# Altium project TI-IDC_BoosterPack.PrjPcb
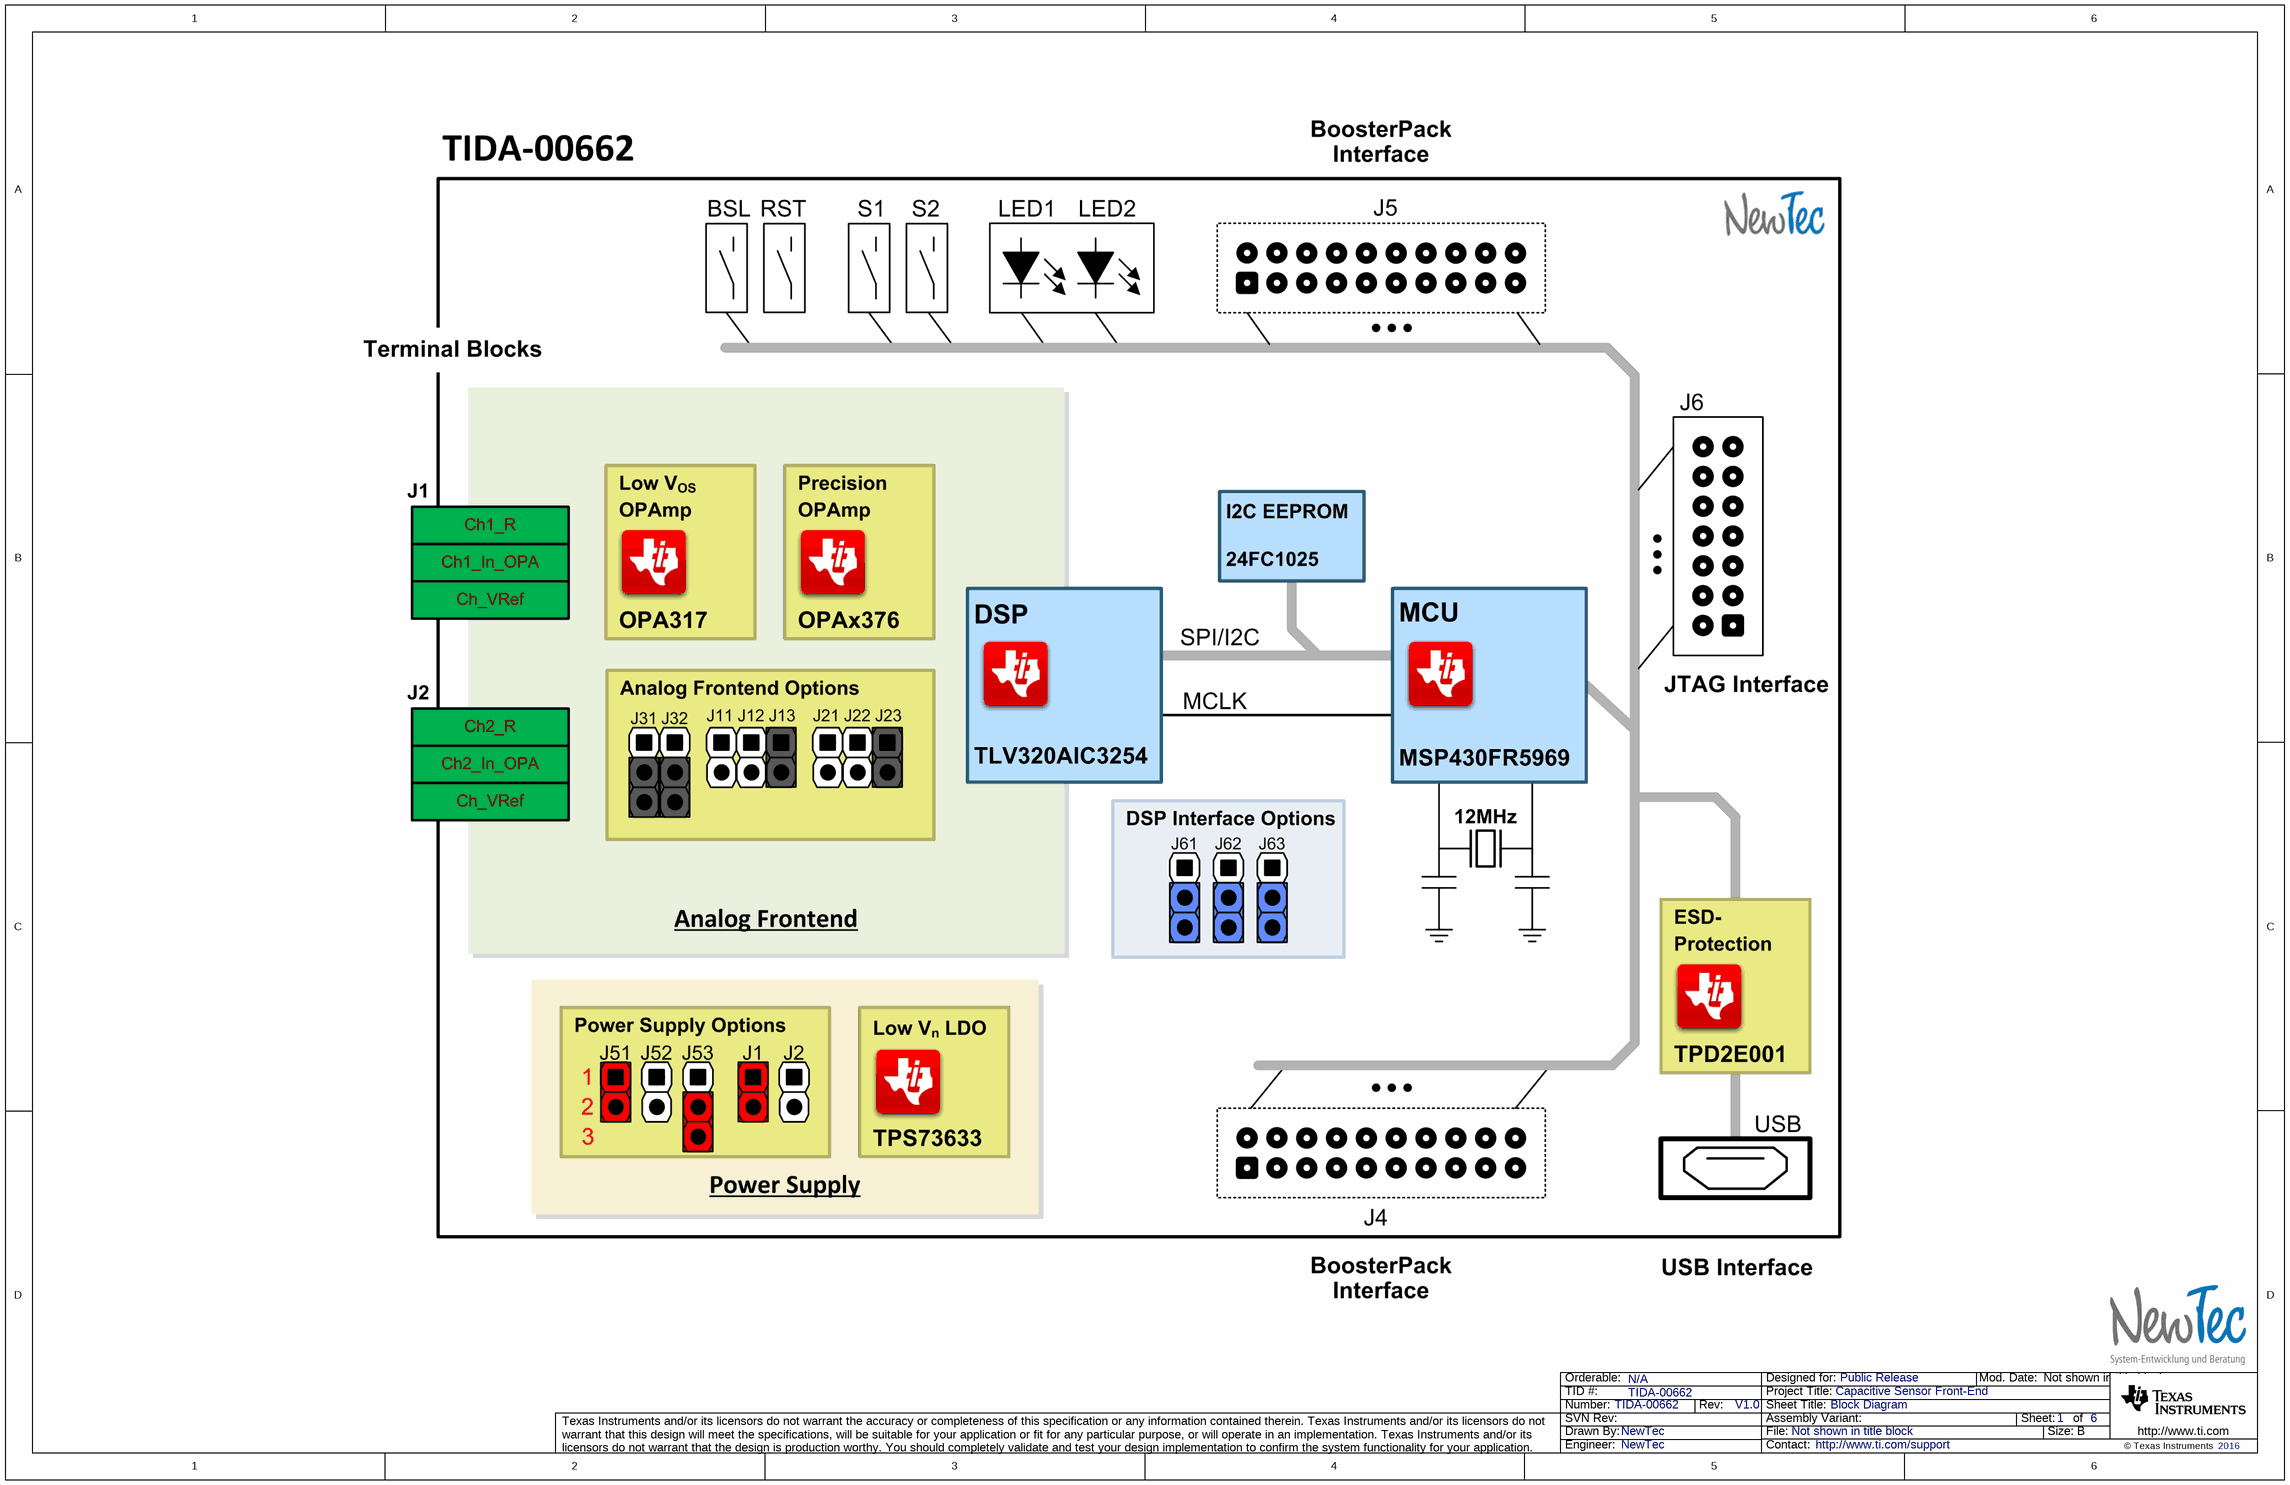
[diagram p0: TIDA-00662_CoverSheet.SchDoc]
CopyrightYear: 2016; EVM_Orderable: N/A; PCB_Layout: NewTec; PCB_Rev: V1.0; PRJ_Customer: Public Release; PRJ_Engineer: NewTec; PRJ_Number: TIDA-00662; PRJ_Title: Capacitive Sensor Front-End; SCH_Rev: V1.0; TechSupport: http://www.ti.com/support; TID: TIDA-00662
6 sheets, 125 parts. Net scope: flat (ports and power ports of the same name join across sheets).
Board file: TIDA-00662_IDC-BosterPack.PcbDoc
Sheets:
  TIDA-00662_CoverSheet.SchDoc
  TIDA-00662_AIC3254.SchDoc
  TIDA-00662_MCU.SchDoc
  TIDA-00662_ExternalInterfaces.SchDoc
  TIDA-00662_PowerSupply.SchDoc
  TIDA-00662_TID_Hardware.SchDoc

## Sheet TIDA-00662_CoverSheet.SchDoc: Block Diagram
size 431 x 279 mm; Date: Not shown in title block; ApprovedBy: Not shown in title block; CheckedBy: Not shown in title block; Author: Not shown in title block; CompanyName: Not shown in title block; DrawnBy: NewTec; Engineer: Not shown in title block; Organization: Not shown in title block; Address1: Not shown in title block; Address2: Not shown in title block; Address3: Not shown in title block; Address4: Not shown in title block; DocumentNumber: 1; Revision: Use project parameter SCH_Rev; SheetNumber: 1; SheetTotal: 6; PageSetup: Record=PageOptions¦CenterHorizontal=True¦CenterVertical=True¦PrintScale=1.00¦XCorrection=1.00¦YCorrection=1.00¦PrintKind=0¦BorderSize=5000000¦LeftOffset=0¦BottomOffset=0¦Orientation=2¦PaperLength=1000¦PaperWidth=1000¦Scale=100¦PaperSource=15¦PrintQuality=600¦MediaType=1¦DitherType=10¦PaperKind=Letter¦PrintScaleMode=1

## Sheet TIDA-00662_AIC3254.SchDoc: Sensor Front-End
size 431 x 279 mm; Date: Not shown in title block; ApprovedBy: Not shown in title block; CheckedBy: Not shown in title block; Author: Not shown in title block; CompanyName: Not shown in title block; DrawnBy: NewTec; Engineer: Not shown in title block; Organization: Not shown in title block; Address1: Not shown in title block; Address2: Not shown in title block; Address3: Not shown in title block; Address4: Not shown in title block; DocumentNumber: 2; Revision: Use project parameter SCH_Rev; SheetNumber: 2; SheetTotal: 6; PageSetup: Record=PageOptions¦CenterHorizontal=True¦CenterVertical=True¦PrintScale=1.00¦XCorrection=1.00¦YCorrection=1.00¦PrintKind=0¦BorderSize=5000000¦LeftOffset=0¦BottomOffset=0¦Orientation=2¦PaperLength=1000¦PaperWidth=1000¦Scale=100¦PaperSource=15¦PrintQuality=600¦MediaType=1¦DitherType=10¦PaperKind=Letter¦PrintScaleMode=1
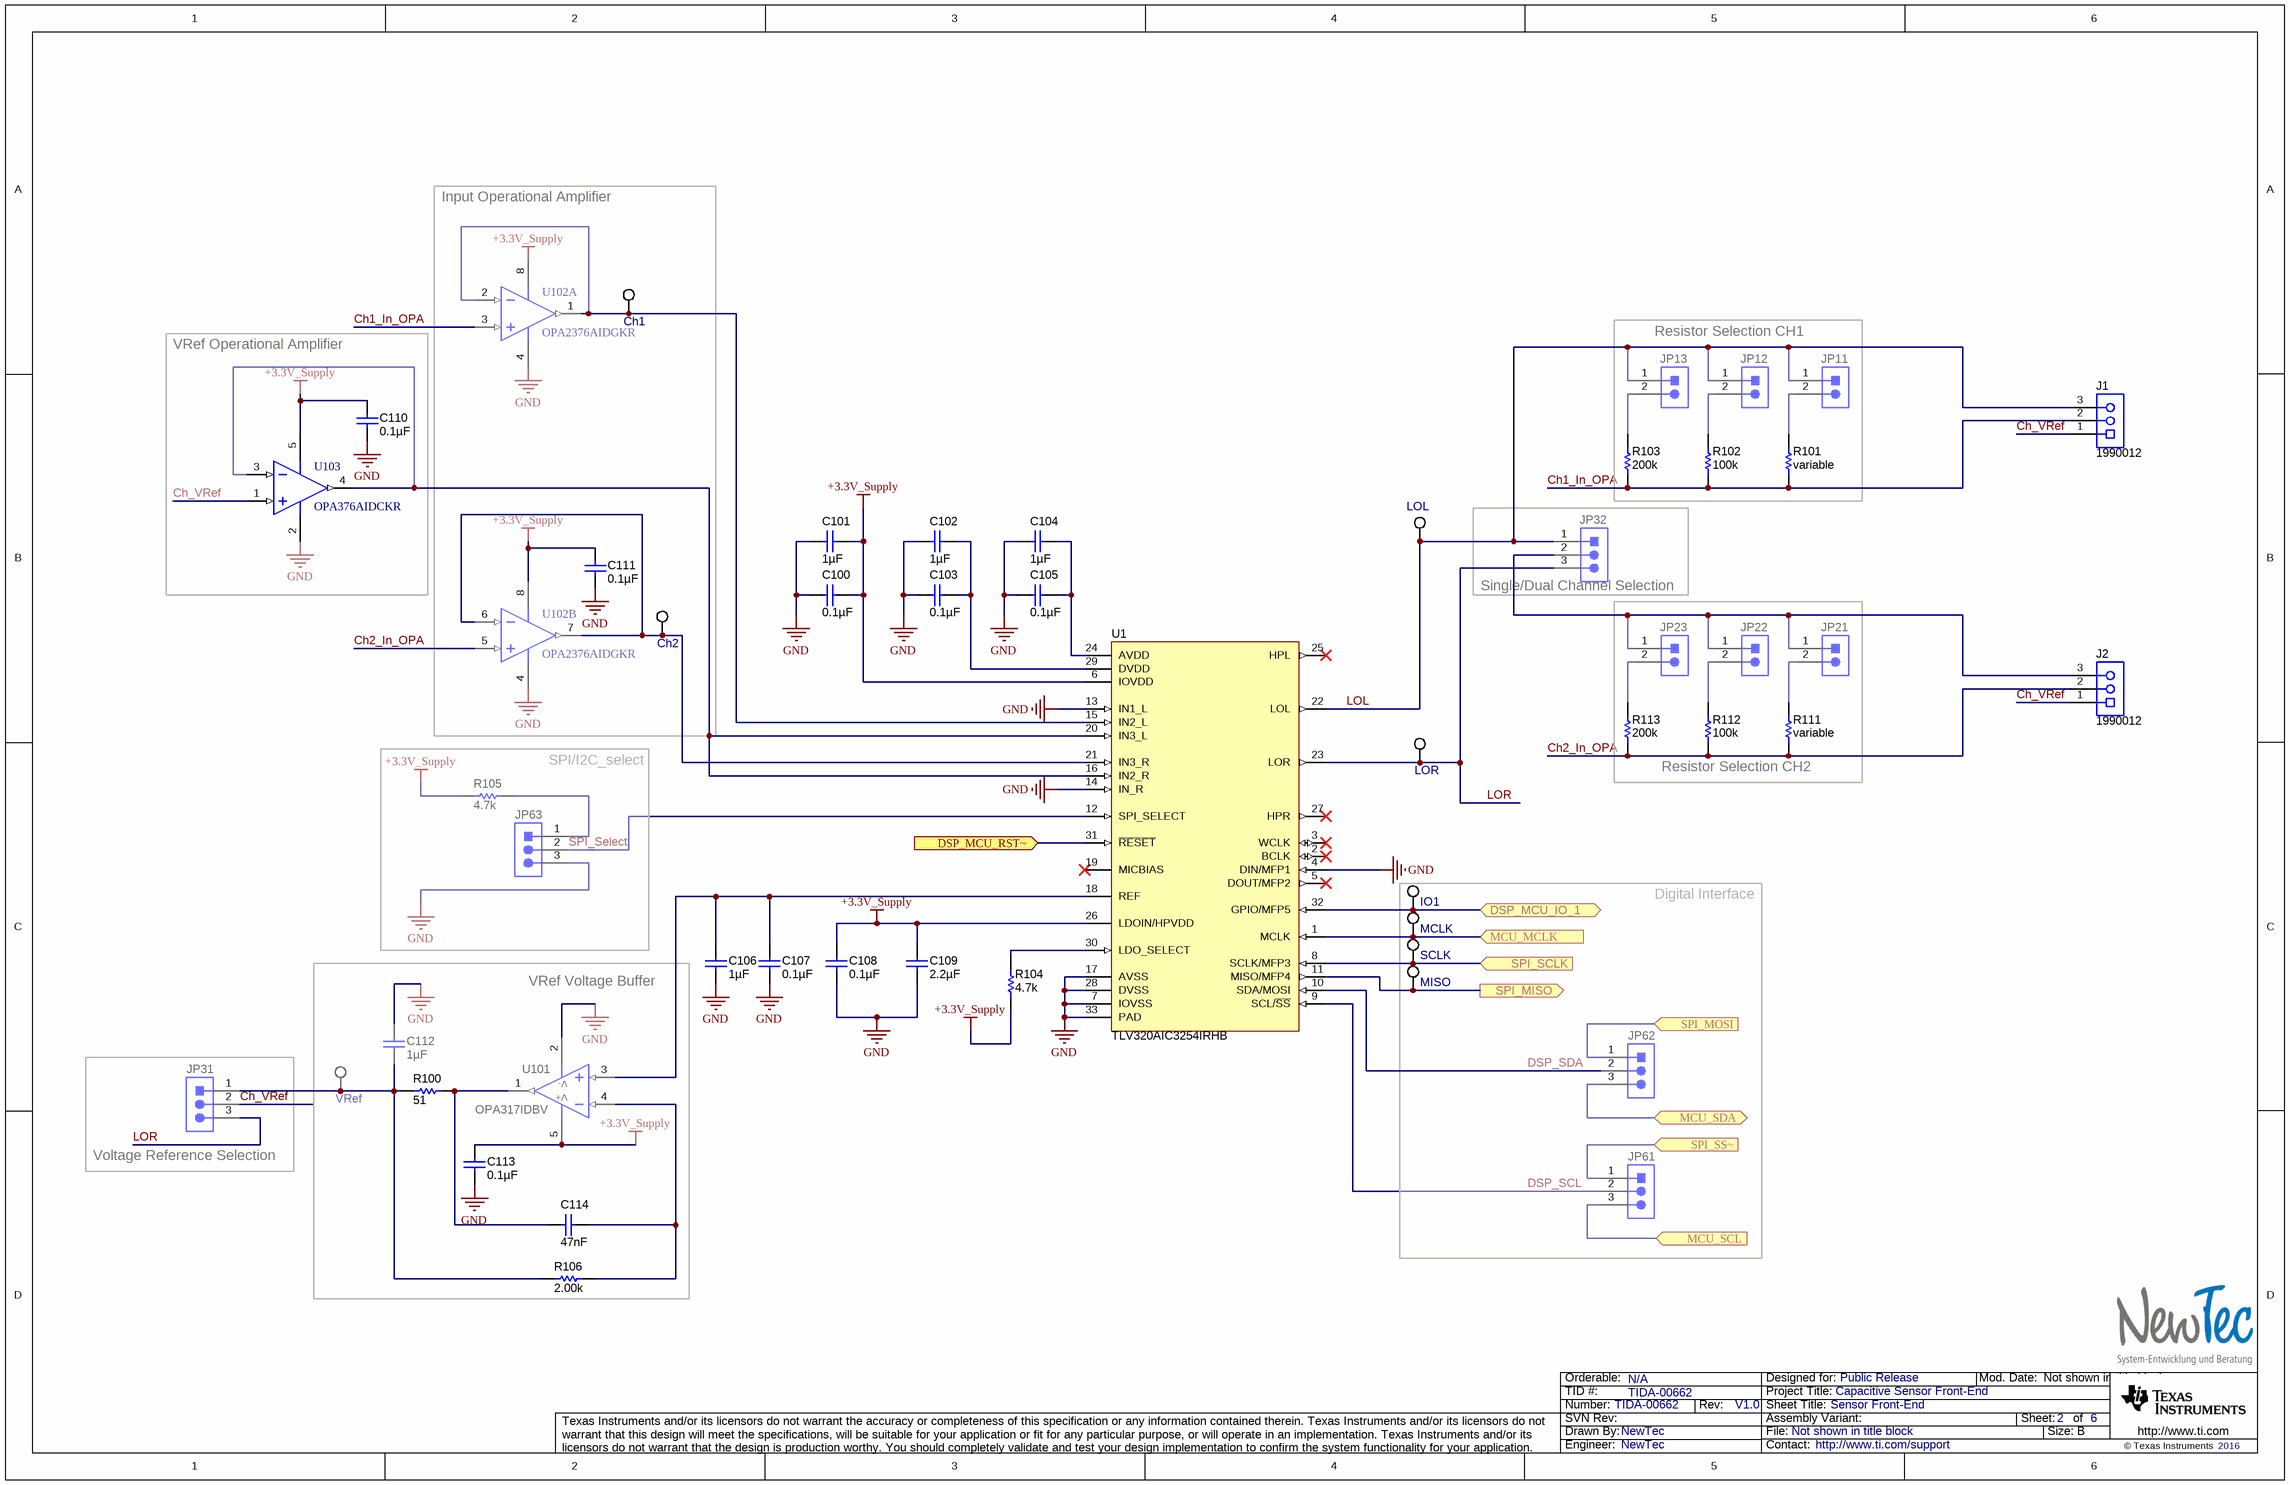
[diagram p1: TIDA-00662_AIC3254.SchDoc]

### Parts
C100  ValueDisplayed: 0.1µF  [0402W]  (hidden comment: 0.1uF)
C101  ValueDisplayed: 1µF  [0603_095]  (hidden comment: 1uF)
C102  ValueDisplayed: 1µF  [0603_095]  (hidden comment: 1uF)
C103  ValueDisplayed: 0.1µF  [0402W]  (hidden comment: 0.1uF)
C104  ValueDisplayed: 1µF  [0603_095]  (hidden comment: 1uF)
C105  ValueDisplayed: 0.1µF  [0402W]  (hidden comment: 0.1uF)
C106  ValueDisplayed: 1µF  [0805_HV]  (hidden comment: 1uF)
C107  ValueDisplayed: 0.1µF  [0402W]  (hidden comment: 0.1uF)
C108  ValueDisplayed: 0.1µF  [0402W]  (hidden comment: 0.1uF)
C109  ValueDisplayed: 2.2µF  [0805_HV]  (hidden comment: 2.2uF)
C110  ValueDisplayed: 0.1µF  [0402W]  (hidden comment: 0.1uF)
C111  ValueDisplayed: 0.1µF  [0402W]  (hidden comment: 0.1uF)
C112  ValueDisplayed: 1µF  [0603_095]  (hidden comment: 1uF)
C113  ValueDisplayed: 0.1µF  [0402W]  (hidden comment: 0.1uF)
C114  47nF  [0402W]
Ch1  5002  [Keystone5002]  (value not drawn)
Ch2  5002  [Keystone5002]  (value not drawn)
IO1  5002  [Keystone5002]  (value not drawn)
J1  1990012  [Phoenix_1990012]
J2  1990012  [Phoenix_1990012]
JP11  61300211121  [WURTH_61300211121]  (value not drawn)
JP12  61300211121  [WURTH_61300211121]  (value not drawn)
JP13  61300211121  [WURTH_61300211121]  (value not drawn)
JP21  61300211121  [WURTH_61300211121]  (value not drawn)
JP22  61300211121  [WURTH_61300211121]  (value not drawn)
JP23  61300211121  [WURTH_61300211121]  (value not drawn)
JP31  61300311121  [WURTH_61300311121]  (value not drawn)
JP32  61300311121  [WURTH_61300311121]  (value not drawn)
JP61  61300311121  [WURTH_61300311121]  (value not drawn)
JP62  61300311121  [WURTH_61300311121]  (value not drawn)
JP63  61300311121  [WURTH_61300311121]  (value not drawn)
LOL  5002  [Keystone5002]  (value not drawn)
LOR  5002  [Keystone5002]  (value not drawn)
MCLK  5002  [Keystone5002]  (value not drawn)
MISO  5002  [Keystone5002]  (value not drawn)
R100  51  [0402W]
R101  ValueDisplayed: variable  [CMF50]  (hidden comment: 150k)
R102  100k  [0805_HV]
R103  200k  [0805_HV]
R104  4.7k  [0402W]
R105  4.7k  [0402W]
R106  2.00k  [0402W]
R111  ValueDisplayed: variable  [CMF50]  (hidden comment: 150k)
R112  100k  [0805_HV]
R113  200k  [0805_HV]
SCLK  5002  [Keystone5002]  (value not drawn)
U1  TLV320AIC3254IRHB  [RHB0032E_NV]
U101  OPA317IDBV  [DBV0005A_N]
U102  OPA2376AIDGKR  [DGK0008A_N]  (parts A,B of 2)
U103  OPA376AIDCKR  [DCK0005A_N]
VRef  5002  [Keystone5002]  (value not drawn)

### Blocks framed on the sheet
Input Operational Amplifier: C111 Ch1 Ch2 U102
Resistor Selection CH1: JP11-JP13 R101-R103
VRef Operational Amplifier: C110 U103
Single/Dual Channel Selection: JP32
Resistor Selection CH2: JP21-JP23 R111-R113
SPI/I2C_select: JP63 R105
Digital Interface: IO1 JP61 JP62 MCLK MISO SCLK
VRef Voltage Buffer: C112-C114 R100 R106 U101 VRef
Voltage Reference Selection: JP31

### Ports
DSP_MCU_IO_1 (bidir), DSP_MCU_RST~ (in), MCU_MCLK (in), MCU_SCL (in), MCU_SDA (bidir), SPI_MISO (out), SPI_MOSI (in), SPI_SCLK (in), SPI_SS~ (in)

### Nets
+3.3V_Supply: C100.2 C101.2 C108.2 C109.1 C110.1 C111.1 C113.1 R104.1 R105.1 U1.6(IOVDD) U1.26(LDOIN/HPVDD) U101.5(V+) U102.8(V+) U103.5(V+)
GND: C100.1 C101.1 C102.1 C103.1 C104.1 C105.1 C106.1 C107.2 C108.1 C109.2 C110.2 C111.2 C112.1 C113.2 JP63.3 U1.4(DIN/MFP1) U1.7(IOVSS) U1.13(IN1_L) U1.14(IN_R) U1.17(AVSS) U1.28(DVSS) U1.33(PAD) U101.2(V-) U102.4(V-) U103.2(V-)
Ch1_In_OPA: J1.2 R101.1 R102.1 R103.1 U102.3(IN_A+)
Ch2_In_OPA: J2.2 R111.1 R112.1 R113.1 U102.5(IN_B+)
Ch_VRef: J1.1 J2.1 JP31.2 U103.1(IN+)
DSP_MCU_IO_1: IO1.1 U1.32(GPIO/MFP5) ; port DSP_MCU_IO_1
DSP_MCU_RST~: U1.31(~{RESET}) ; port DSP_MCU_RST~
DSP_SCL: JP61.2 U1.9(SCL/~{SS})
DSP_SDA: JP62.2 U1.10(SDA/MOSI)
LOL: J1.3 JP11.1 JP12.1 JP13.1 JP32.1 LOL.1 U1.22(LOL)
LOR: JP31.3 JP32.3 LOR.1 U1.23(LOR)
MCU_MCLK: MCLK.1 U1.1(MCLK) ; port MCU_MCLK
MCU_SCL: JP61.3 ; port MCU_SCL
MCU_SDA: JP62.3 ; port MCU_SDA
SPI_MISO: MISO.1 U1.11(MISO/MFP4) ; port SPI_MISO
SPI_MOSI: JP62.1 ; port SPI_MOSI
SPI_SCLK: SCLK.1 U1.8(SCLK/MFP3) ; port SPI_SCLK
SPI_Select: JP63.2 U1.12(SPI_SELECT)
SPI_SS~: JP61.1 ; port SPI_SS~
NetC102_2: C102.2 C103.2 U1.29(DVDD)
NetC104_2: C104.2 C105.2 U1.24(AVDD)
NetC106_2: C106.2 C107.1 U1.18(REF) U101.3(IN+)
NetC112_2: C112.2 JP31.1 R100.1 R106.1 VRef.1
NetC114_1: C114.1 R106.2 U101.4(IN-)
NetC114_2: C114.2 R100.2 U101.1(OUT)
NetCh1_1: Ch1.1 U1.15(IN2_L) U102.1(OUT_A) U102.2(IN_A-)
NetCh2_1: Ch2.1 U1.21(IN3_R) U102.6(IN_B-) U102.7(OUT_B)
NetJ2_3: J2.3 JP21.1 JP22.1 JP23.1 JP32.2
NetJP11_2: JP11.2 R101.2
NetJP12_2: JP12.2 R102.2
NetJP13_2: JP13.2 R103.2
NetJP21_2: JP21.2 R111.2
NetJP22_2: JP22.2 R112.2
NetJP23_2: JP23.2 R113.2
NetJP63_1: JP63.1 R105.2
NetR104_2: R104.2 U1.30(LDO_SELECT)
NetU1_16: U1.16(IN2_R) U1.20(IN3_L) U103.3(IN-) U103.4(OUT)

Not connected (* = marked no-connect by the designer): U1 2(BCLK)* 3(WCLK)* 5(DOUT/MFP2)* 19(MICBIAS)* 25(HPL)* 27(HPR)*

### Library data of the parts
C100 C103 C105 C107 C108 C110 C111 C113 = 885012205037: CAP, CERM, 0.1 µF, 16 V, +/- 10%, X7R, 0402; Manufacturer: Wurth Elektronik; Polarized: N; CompType: Capacitor; U/M: EA; Cap_F: 0.0000001; Tolerance_%: 10; Value1: Unknown; VDC_V: 16; Value2: 16V; TaMin_C: -55; TaMax_C: 125; Cap_Case: 0402
C101 C102 C104 C112 = 885012206052: CAP, CERM, 1 µF, 16 V, +/- 10%, X7R, 0603_095; Manufacturer: Wurth Elektronik; Polarized: N; CompType: Capacitor; U/M: EA; Cap_F: 0.000001; Tolerance_%: 10; Value1: Unknown; VDC_V: 16; Value2: 16V; TaMin_C: -55; TaMax_C: 125; Cap_Case: 0603
C106 = 08055C105KAT2A: CAP, CERM, 1 µF, 50 V, +/- 10%, X7R, 0805; Manufacturer: AVX; Polarized: N; CompType: Capacitor; U/M: EA; Cap_F: 0.000001; Tolerance_%: 10; Value1: Unknown; VDC_V: 50; Value2: 50V; TaMin_C: -55; TaMax_C: 125; Cap_Case: 0805
C109 = 0805YD225KAT2A: CAP, CERM, 2.2 µF, 16 V, +/- 10%, X5R, 0805; Manufacturer: AVX; Polarized: N; CompType: Capacitor; U/M: EA; Cap_F: 0.0000022; Tolerance_%: 10; ESR_ohm: 0.009; Value1: 0.009 ohm; VDC_V: 16; Value2: 16V; TaMin_C: -55; TaMax_C: 85; Cap_Case: 0805
C114 = 885012205035: CAP, CERM, 47 nF, 16 V, +/- 10%, X7R 0402; Manufacturer: Wurth Elektronik; Polarized: N; CompType: Capacitor; U/M: EA; Cap_F: 0.000000047; Tolerance_%: 5; Value1: Unknown; VDC_V: 16; Value2: 16V; TempCo: C0G/NP0; TaMin_C: -55; TaMax_C: 125; Cap_Case: 0402
Ch1 Ch2 IO1 LOL LOR MCLK MISO SCLK VRef = 5002: Test Point, Miniature, White, TH; Manufacturer: Keystone; CompType: Test Point Loop; U/M: EA
J1 J2 = 1990012: Terminal Block, 2.5mm, 3 Pos, TH; Manufacturer: Phoenix Contact; SymbolCreator: a0412235; Pitch_mm: 2.54; Gender: Female; Row_Count: 1; Current_A: 2; Voltage_V: 400; Cert_CULUS: Y
JP11-JP13 JP21-JP23 = 61300211121: Header, 2.54 mm, 2x1, Gold, TH; Manufacturer: Wurth Elektronik; SymbolCreator: a0412235; U/M: EA
JP31 JP32 JP61-JP63 = 61300311121: Header, 2.54 mm, 3x1, Gold, TH; Manufacturer: Wurth Elektronik; SymbolCreator: a0799628; U/M: EA
R100 = CRCW040251R0JNED: RES, 51, 5%, 0.063 W, 0402; Manufacturer: Vishay-Dale; CompType: Resistor; Value_Code: 51R0; Tolerance_%: 5; Power_W: 0.063; Value2: 0.063W; VDC_V: 50; TempCo: 200 ppm/C; EIA_Code: E24; U/M: EA
R101 R111 = CMF50150K00FHEB: RES, 150 k, 1%, 0.25 W, TH; Manufacturer: Vishay-Dale; CompType: Resistor; Res_ohm: 150000; Tolerance_%: 1; Power_W: 0.25; Value2: 0.25W; VDC_V: 200; TempCo: 50 ppm/C; EIA_Code: E96; U/M: EA
R102 R112 = CRCW0805100KFKEA: RES, 100 k, 1%, 0.125 W, 0805; Manufacturer: Vishay-Dale; CompType: Resistor; Res_ohm: 100000; Tolerance_%: 1; Power_W: 0.125; Value2: 0.125W; VDC_V: 150; TempCo: 100 ppm/C; EIA_Code: E96; U/M: EA
R103 R113 = CRCW0805200KFKEA: RES, 200 k, 1%, 0.125 W, 0805; Manufacturer: Vishay-Dale; CompType: Resistor; Res_ohm: 200000; Tolerance_%: 1; Power_W: 0.125; Value2: 0.125W; VDC_V: 150; TempCo: 100 ppm/C; EIA_Code: E96; U/M: EA
R104 R105 = CRCW04024K70JNED: RES, 4.7 k, 5%, 0.063 W, 0402; Manufacturer: Vishay-Dale; CompType: Resistor; Res_ohm: 4700; Value_Code: 4k70; Tolerance_%: 5; Power_W: 0.063; Value2: 0.063W; VDC_V: 50; TempCo: 200 ppm/C; EIA_Code: E24; U/M: EA
R106 = CRCW04022K00FKED: RES, 2.00 k, 1%, 0.063 W, 0402; Manufacturer: Vishay-Dale; CompType: Resistor; Res_ohm: 2000; Value_Code: 2k00; Tolerance_%: 1; Power_W: 0.063; Value2: 0.063W; VDC_V: 50; TempCo: 100 ppm/C; EIA_Code: E96; U/M: EA
U1 = TLV320AIC3254IRHB: Ultra Low Power Stereo Audio Codec With Embedded miniDSP, RHB0032E; Manufacturer: Texas Instruments; SymbolCreator: a0411947; CompType: IC; U/M: EA
U101 = OPA317IDBV: Low-Offset, Rail-to-Rail I/O Operational Amplifier, DBV0005A; Manufacturer: Texas Instruments; CompType: IC; U/M: EA
U102 = OPA2376AIDGKR: Precision, Low Noise, Low Quiescent Current Operational Amplifier, 2 to 5.5 V, -40 to 125 degC, 8-pin SOP (DGK0008A), Green (RoHS & no Sb/Br); Manufacturer: Texas Instruments; Alternate PartNumber: Equivalent; CMRR(Min)(dB): 76; IIB(Max)(pA): 10; Iq per channel(Max)(mA): 0.95; Number of Channels: 2; Offset Drift(Typ)(uV/C): 0.32; Sub Family: Low Input Bias Current Amp (<=10pA), Low Noise Amp (<=10nV/rtHz), Low Offset Voltage Amplifier (<=500uV), Low Supply Voltage Amplifier (<=2.7V), Precision Amplifier; Total Supply Voltage(Max)(+5V is 5, +/-5V is 10): 5.5; Vio (25C)(Max)(mV): 0.025; Vn at 1kHz(Typ)(nV/rtHz): 7.5
U103 = OPA376AIDCKR: Precision, Low Noise, Low Iq Operational Amplifier, 2.2 to 5.5 V, -40 to 125 degC, 5-pin SOT23 (DCK0005A), Green (RoHS & no Sb/Br); Manufacturer: Texas Instruments; Alternate PartNumber: Equivalent; CMRR(Min)(dB): 76; IIB(Max)(pA): 10; Iq per channel(Max)(mA): 0.95; Number of Channels: 1; Offset Drift(Typ)(uV/C): 0.32; Slew Rate(Typ)(V/us): 2; Sub Family: Low Input Bias Current Amp (<=10pA), Low Noise Amp (<=10nV/rtHz), Low Offset Voltage Amplifier (<=500uV), Low Supply Voltage Amplifier (<=2.7V), Precision Amplifier; Total Supply Voltage(Max)(+5V is 5, +/-5V is 10): 5.5; Total Supply Voltage(Min)(+5V is 5, +/-5V is 10): 2.2; Vio (25C)(Max)(mV): 0.025; Vn at 1kHz(Typ)(nV/rtHz): 7.5

## Sheet TIDA-00662_MCU.SchDoc: MCU
size 431 x 279 mm; Date: Not shown in title block; ApprovedBy: Not shown in title block; CheckedBy: Not shown in title block; Author: Not shown in title block; CompanyName: Not shown in title block; DrawnBy: NewTec; Engineer: Not shown in title block; Organization: Not shown in title block; Address1: Not shown in title block; Address2: Not shown in title block; Address3: Not shown in title block; Address4: Not shown in title block; DocumentNumber: 3; Revision: Use project parameter SCH_Rev; SheetNumber: 3; SheetTotal: 6; PageSetup: Record=PageOptions¦CenterHorizontal=True¦CenterVertical=True¦PrintScale=1.00¦XCorrection=1.00¦YCorrection=1.00¦PrintKind=0¦BorderSize=5000000¦LeftOffset=0¦BottomOffset=0¦Orientation=2¦PaperLength=1000¦PaperWidth=1000¦Scale=100¦PaperSource=15¦PrintQuality=600¦MediaType=1¦DitherType=10¦PaperKind=Letter¦PrintScaleMode=1
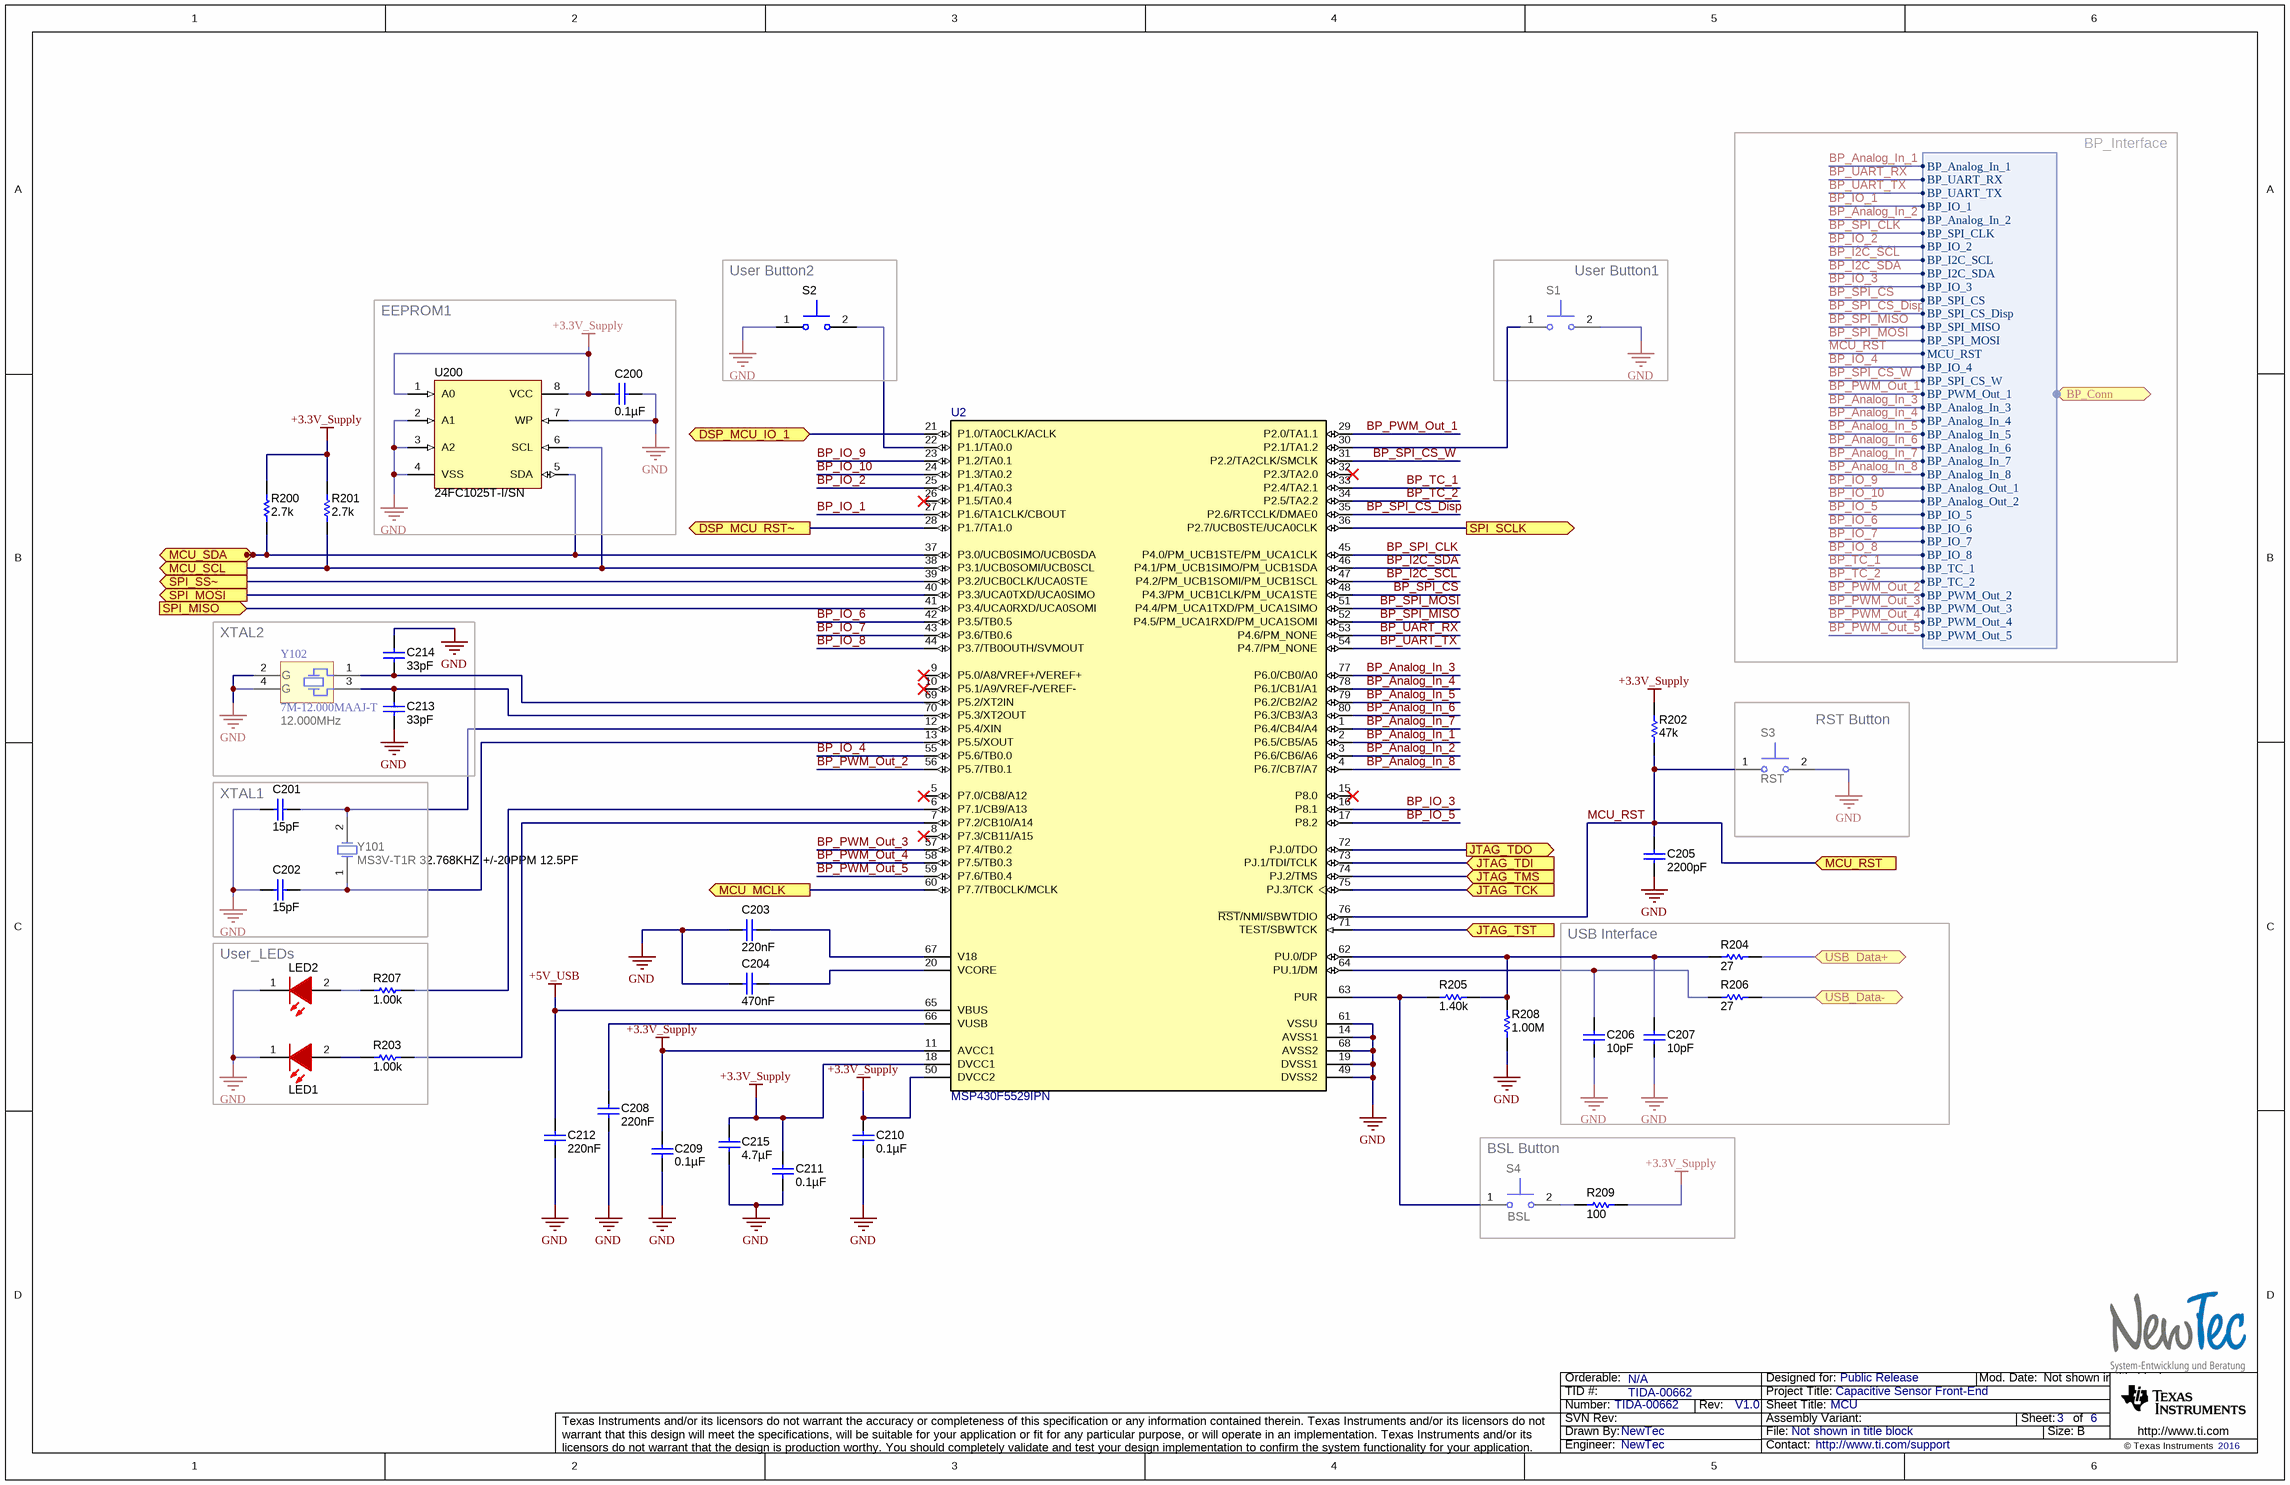
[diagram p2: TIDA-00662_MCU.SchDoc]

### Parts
C200  ValueDisplayed: 0.1µF  [0402W]  (hidden comment: 0.1uF)
C201  15pF  [0402W]
C202  15pF  [0402W]
C203  ValueDisplayed: 220nF  [0603_095]  (hidden comment: 0.22uF)
C204  470nF  [0603_095]
C205  2200pF  [0402W]
C206  10pF  [0402W]
C207  10pF  [0402W]
C208  ValueDisplayed: 220nF  [0603_095]  (hidden comment: 0.22uF)
C209  ValueDisplayed: 0.1µF  [0402W]  (hidden comment: 0.1uF)
C210  ValueDisplayed: 0.1µF  [0402W]  (hidden comment: 0.1uF)
C211  ValueDisplayed: 0.1µF  [0402W]  (hidden comment: 0.1uF)
C212  ValueDisplayed: 220nF  [0603_095]  (hidden comment: 0.22uF)
C213  33pF  [0402W]
C214  33pF  [0402W]
C215  ValueDisplayed: 4.7µF  [0805_145]  (hidden comment: 4.7uF)
LED1  150120RS75000  [WL_SMCW_RED_1206]  (value not drawn)
LED2  150120RS75000  [WL_SMCW_RED_1206]  (value not drawn)
R200  2.7k  [0402W]
R201  2.7k  [0402W]
R202  47k  [0402W]
R203  1.00k  [0402W]
R204  27  [0402W]
R205  1.40k  [0402W]
R206  27  [0402W]
R207  1.00k  [0402W]
R208  ValueDisplayed: 1.00M  [0603_095]  (hidden comment: 1.00Meg)
R209  100  [0402W]
S1  TL1015AF160QG  [SW_TL1015AF160QG]  (value not drawn)
S2  TL1015AF160QG  [SW_TL1015AF160QG]  (value not drawn)
S3  RST  [SW_TL1015AF160QG]
S4  BSL  [SW_TL1015AF160QG]
U2  MSP430F5529IPN  [PN0080A_N]
U200  24FC1025T-I/SN  [SOIC-8]
Y101  MS3V-T1R 32.768KHZ +/-20PPM 12.5PF  [XTAL_MS3V-T1R]
Y102  7M-12.000MAAJ-T  Frequency: 12.000MHz  [TXC_7M]

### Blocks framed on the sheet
User Button2: S2
User Button1: S1
EEPROM1: C200 U200
XTAL2: C213 C214 Y102
RST Button: S3
XTAL1: C201 C202 Y101
User_LEDs: LED1 LED2 R203 R207
USB Interface: C206 C207 R204 R206
BSL Button: R209 S4

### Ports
BP_Conn (harness BP_Conn), DSP_MCU_IO_1 (bidir), DSP_MCU_RST~ (out), JTAG_TCK (in), JTAG_TDI (in), JTAG_TDO (out), JTAG_TMS (in), JTAG_TST (in), MCU_MCLK (out), MCU_RST (in), MCU_SCL (out), MCU_SDA (bidir), SPI_MISO (in), SPI_MOSI (out), SPI_SCLK (out), SPI_SS~ (out), USB_Data+ (bidir), USB_Data- (bidir)

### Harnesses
BP_Conn: BP_Analog_In_1, BP_UART_RX, BP_UART_TX, BP_IO_1, BP_Analog_In_2, BP_SPI_CLK, BP_IO_2, BP_I2C_SCL, BP_I2C_SDA, BP_IO_3, BP_SPI_CS, BP_SPI_CS_Disp, BP_SPI_MISO, BP_SPI_MOSI, MCU_RST, BP_IO_4, BP_SPI_CS_W, BP_PWM_Out_1, BP_Analog_In_3, BP_Analog_In_4, BP_Analog_In_5, BP_Analog_In_6, BP_Analog_In_7, BP_Analog_In_8, BP_Analog_Out_1, BP_Analog_Out_2, BP_IO_5, BP_IO_6, BP_IO_7, BP_IO_8, BP_TC_1, BP_TC_2, BP_PWM_Out_2, BP_PWM_Out_3, BP_PWM_Out_4, BP_PWM_Out_5

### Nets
+3.3V_Supply: C200.2 C209.1 C210.1 C211.1 C215.1 R200.2 R201.2 R202.2 R209.2 U2.11(AVCC1) U2.18(DVCC1) U2.50(DVCC2) U200.1(A0) U200.8(VCC)
+5V_USB: C212.2 U2.65(VBUS)
GND: C200.1 C201.2 C202.2 C203.1 C204.1 C205.2 C206.2 C207.2 C208.1 C209.2 C210.2 C211.2 C212.1 C213.2 C214.1 C215.2 LED1.1(K) LED2.1(K) R208.1 S1.2 S2.1 S3.2 U2.14(AVSS1) U2.19(DVSS1) U2.49(DVSS2) U2.61(VSSU) U2.68(AVSS2) U200.2(A1) U200.3(A2) U200.4(VSS) U200.7(WP) Y102.2(GND) Y102.4(GND)
BP_Analog_In_1: U2.2(P6.5/CB5/A5) ; port BP_Conn.BP_Analog_In_1
BP_Analog_In_2: U2.3(P6.6/CB6/A6) ; port BP_Conn.BP_Analog_In_2
BP_Analog_In_3: U2.77(P6.0/CB0/A0) ; port BP_Conn.BP_Analog_In_3
BP_Analog_In_4: U2.78(P6.1/CB1/A1) ; port BP_Conn.BP_Analog_In_4
BP_Analog_In_5: U2.79(P6.2/CB2/A2) ; port BP_Conn.BP_Analog_In_5
BP_Analog_In_6: U2.80(P6.3/CB3/A3) ; port BP_Conn.BP_Analog_In_6
BP_Analog_In_7: U2.1(P6.4/CB4/A4) ; port BP_Conn.BP_Analog_In_7
BP_Analog_In_8: U2.4(P6.7/CB7/A7) ; port BP_Conn.BP_Analog_In_8
BP_I2C_SCL: U2.47(P4.2/PM_UCB1SOMI/PM_UCB1SCL) ; port BP_Conn.BP_I2C_SCL
BP_I2C_SDA: U2.46(P4.1/PM_UCB1SIMO/PM_UCB1SDA) ; port BP_Conn.BP_I2C_SDA
BP_IO_1: U2.27(P1.6/TA1CLK/CBOUT) ; port BP_Conn.BP_IO_1
BP_IO_2: U2.25(P1.4/TA0.3) ; port BP_Conn.BP_IO_2
BP_IO_3: U2.16(P8.1) ; port BP_Conn.BP_IO_3
BP_IO_4: U2.55(P5.6/TB0.0) ; port BP_Conn.BP_IO_4
BP_IO_5: U2.17(P8.2) ; port BP_Conn.BP_IO_5
BP_IO_6: U2.42(P3.5/TB0.5) ; port BP_Conn.BP_IO_6
BP_IO_7: U2.43(P3.6/TB0.6) ; port BP_Conn.BP_IO_7
BP_IO_8: U2.44(P3.7/TB0OUTH/SVMOUT) ; port BP_Conn.BP_IO_8
BP_IO_9: U2.23(P1.2/TA0.1) ; port BP_Conn.BP_Analog_Out_1
BP_IO_10: U2.24(P1.3/TA0.2) ; port BP_Conn.BP_Analog_Out_2
BP_PWM_Out_1: U2.29(P2.0/TA1.1) ; port BP_Conn.BP_PWM_Out_1
BP_PWM_Out_2: U2.56(P5.7/TB0.1) ; port BP_Conn.BP_PWM_Out_2
BP_PWM_Out_3: U2.57(P7.4/TB0.2) ; port BP_Conn.BP_PWM_Out_3
BP_PWM_Out_4: U2.58(P7.5/TB0.3) ; port BP_Conn.BP_PWM_Out_4
BP_PWM_Out_5: U2.59(P7.6/TB0.4) ; port BP_Conn.BP_PWM_Out_5
BP_SPI_CLK: U2.45(P4.0/PM_UCB1STE/PM_UCA1CLK) ; port BP_Conn.BP_SPI_CLK
BP_SPI_CS: U2.48(P4.3/PM_UCB1CLK/PM_UCA1STE) ; port BP_Conn.BP_SPI_CS
BP_SPI_CS_Disp: U2.35(P2.6/RTCCLK/DMAE0) ; port BP_Conn.BP_SPI_CS_Disp
BP_SPI_CS_W: U2.31(P2.2/TA2CLK/SMCLK) ; port BP_Conn.BP_SPI_CS_W
BP_SPI_MISO: U2.52(P4.5/PM_UCA1RXD/PM_UCA1SOMI) ; port BP_Conn.BP_SPI_MISO
BP_SPI_MOSI: U2.51(P4.4/PM_UCA1TXD/PM_UCA1SIMO) ; port BP_Conn.BP_SPI_MOSI
BP_TC_1: U2.33(P2.4/TA2.1) ; port BP_Conn.BP_TC_1
BP_TC_2: U2.34(P2.5/TA2.2) ; port BP_Conn.BP_TC_2
BP_UART_RX: U2.53(P4.6/PM_NONE) ; port BP_Conn.BP_UART_RX
BP_UART_TX: U2.54(P4.7/PM_NONE) ; port BP_Conn.BP_UART_TX
DSP_MCU_IO_1: U2.21(P1.0/TA0CLK/ACLK) ; port DSP_MCU_IO_1
DSP_MCU_RST~: U2.28(P1.7/TA1.0) ; port DSP_MCU_RST~
JTAG_TCK: U2.75(PJ.3/TCK) ; port JTAG_TCK
JTAG_TDI: U2.73(PJ.1/TDI/TCLK) ; port JTAG_TDI
JTAG_TDO: U2.72(PJ.0/TDO) ; port JTAG_TDO
JTAG_TMS: U2.74(PJ.2/TMS) ; port JTAG_TMS
JTAG_TST: U2.71(TEST/SBWTCK) ; port JTAG_TST
MCU_MCLK: U2.60(P7.7/TB0CLK/MCLK) ; port MCU_MCLK
MCU_RST: C205.1 R202.1 S3.1 U2.76(~{RST}/NMI/SBWTDIO) ; port MCU_RST, port BP_Conn.MCU_RST
MCU_SCL: R201.1 U2.38(P3.1/UCB0SOMI/UCB0SCL) U200.6(SCL) ; port MCU_SCL
MCU_SDA: R200.1 U2.37(P3.0/UCB0SIMO/UCB0SDA) U200.5(SDA) ; port MCU_SDA
SPI_MISO: U2.41(P3.4/UCA0RXD/UCA0SOMI) ; port SPI_MISO
SPI_MOSI: U2.40(P3.3/UCA0TXD/UCA0SIMO) ; port SPI_MOSI
SPI_SCLK: U2.36(P2.7/UCB0STE/UCA0CLK) ; port SPI_SCLK
SPI_SS~: U2.39(P3.2/UCB0CLK/UCA0STE) ; port SPI_SS~
USB_Data+: R204.2 ; port USB_Data+
USB_Data-: R206.2 ; port USB_Data-
NetC201_1: C201.1 U2.12(P5.4/XIN) Y101.2(OSC2)
NetC202_1: C202.1 U2.13(P5.5/XOUT) Y101.1(OSC1)
NetC203_2: C203.2 U2.67(V18)
NetC204_2: C204.2 U2.20(VCORE)
NetC206_1: C206.1 R206.1 U2.64(PU.1/DM)
NetC207_1: C207.1 R204.1 R205.2 R208.2 U2.62(PU.0/DP)
NetC208_2: C208.2 U2.66(VUSB)
NetC213_1: C213.1 U2.70(P5.3/XT2OUT) Y102.3
NetC214_2: C214.2 U2.69(P5.2/XT2IN) Y102.1
NetLED1_2: LED1.2(A) R203.1
NetLED2_2: LED2.2(A) R207.1
NetR203_2: R203.2 U2.7(P7.2/CB10/A14)
NetR205_1: R205.1 S4.1 U2.63(PUR)
NetR207_2: R207.2 U2.6(P7.1/CB9/A13)
NetR209_1: R209.1 S4.2
NetS1_1: S1.1 U2.30(P2.1/TA1.2)
NetS2_2: S2.2 U2.22(P1.1/TA0.0)

Not connected (* = marked no-connect by the designer): U2 5(P7.0/CB8/A12)* 8(P7.3/CB11/A15)* 9(P5.0/A8/VREF+/VEREF+)* 10(P5.1/A9/VREF-/VEREF-)* 15(P8.0)* 26(P1.5/TA0.4)* 32(P2.3/TA2.0)*

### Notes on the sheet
- BP_Interface

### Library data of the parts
C200 C209-C211 = 885012205037: as C100 on sheet TIDA-00662_AIC3254
C201 C202 = 885012005056: CAP, CERM, 15 pF, 50 V, +/- 5%, C0G/NP0, 0402; Manufacturer: Wurth Elektronik; Polarized: N; CompType: Capacitor; U/M: EA; Cap_F: 0.000000000015; Tolerance_%: 5; Value1: Unknown; VDC_V: 50; Value2: 50V; TaMin_C: -55; TaMax_C: 125; Cap_Case: 0402
C203 C208 C212 = 885012206048: CAP, CERM, 0.22 µF, 16 V, +/- 10%, X7R, 0603_095; Manufacturer: Wurth Elektronik; Polarized: N; CompType: Capacitor; U/M: EA; Cap_F: 0.00000022; Tolerance_%: 10; Value1: Unknown; VDC_V: 16; Value2: 16V; TaMin_C: -55; TaMax_C: 125; Cap_Case: 0603
C204 = 885012206050: CAP, CERM, 470 nF, 16 V, +/- 10%, X7R, 0603_095; Manufacturer: Wurth Elektronik; Polarized: N; CompType: Capacitor; U/M: EA; Cap_F: 0.000000470; Tolerance_%: 10; Value1: Unknown; VDC_V: 16; Value2: 16V; TaMin_C: -55; TaMax_C: 125; Cap_Case: 0603
C205 = 885012205027: CAP, CERM, 2200 pF, 16 V, +/- 10%, X7R, 0402; Manufacturer: Wurth Elektronik; Polarized: N; CompType: Capacitor; U/M: EA; Cap_F: 0.0000000022; Tolerance_%: 10; Value1: Unknown; VDC_V: 16; Value2: 16V; TaMin_C: -55; TaMax_C: 125; Cap_Case: 0402
C206 C207 = 885012005025: CAP, CERM, 10 pF, 16 V, +/- 5%, C0G/NP0, 0402; Manufacturer: Wurth Elektronik; Polarized: N; CompType: Capacitor; U/M: EA; Cap_F: 0.000000000010; Tolerance_%: 5; Value1: Unknown; VDC_V: 16; Value2: 16V; TaMin_C: -55; TaMax_C: 125; Cap_Case: 0402
C213 C214 = 885012005043: CAP, CERM, 33 pF, 25 V, +/- 5%, C0G/NP0, 0402; Manufacturer: Wurth Elektronik; Polarized: N; CompType: Capacitor; U/M: EA; Cap_F: 0.000000000033; Tolerance_%: 5; Value1: Unknown; VDC_V: 25; Value2: 25V; TaMin_C: -55; TaMax_C: 125; Cap_Case: 0402
C215 = 885012207025: CAP, CERM, 4.7 µF, 10 V, +/- 10%, X7R, 0805; Manufacturer: Wurth Elektronik; Polarized: N; CompType: Capacitor; U/M: EA; Cap_F: 0.0000047; Tolerance_%: 10; Value1: Unknown; Value2: 10V; TaMin_C: -55; TaMax_C: 125; Cap_Case: 0805
LED1 LED2 = 150120RS75000: LED, Red, SMD; Manufacturer: Wurth Elektronik; SymbolCreator: Altium; Type: AlInGaP; Vf_V: 2; Value2: 2V; Io_A: 0.02; Vr_V: 5; Ir_A: 1e-005; Tjmax_C: 85; Power_TotalModule: 0.072; Value1: 0.072W; Angle: 140; U/M: EA
R200 R201 = CRCW04022K70JNED: RES, 2.7 k, 5%, 0.063 W, 0402; Manufacturer: Vishay-Dale; CompType: Resistor; Res_ohm: 2700; Value_Code: 2k70; Tolerance_%: 5; Power_W: 0.063; Value2: 0.063W; VDC_V: 50; TempCo: 200 ppm/C; EIA_Code: E24; U/M: EA
R202 = CRCW040247K0JNED: RES, 47 k, 5%, 0.063 W, 0402; Manufacturer: Vishay-Dale; CompType: Resistor; Res_ohm: 47000; Value_Code: 47k0; Tolerance_%: 5; Power_W: 0.063; Value2: 0.063W; VDC_V: 50; TempCo: 200 ppm/C; EIA_Code: E24; U/M: EA
R203 R207 = CRCW04021K00FKED: RES, 1.00 k, 1%, 0.063 W, 0402; Manufacturer: Vishay-Dale; CompType: Resistor; Res_ohm: 1000; Value_Code: 1k00; Tolerance_%: 1; Power_W: 0.063; Value2: 0.063W; VDC_V: 50; TempCo: 100 ppm/C; EIA_Code: E96; U/M: EA; AEC Category: Q200
R204 R206 = CRCW040227R0JNED: RES, 27, 5%, 0.063 W, 0402; Manufacturer: Vishay-Dale; CompType: Resistor; Value_Code: 27R0; Tolerance_%: 5; Power_W: 0.063; Value2: 0.063W; VDC_V: 50; TempCo: 200 ppm/C; EIA_Code: E24; U/M: EA
R205 = CRCW04021K40FKED: RES, 1.40 k, 1%, 0.063 W, 0402; Manufacturer: Vishay-Dale; CompType: Resistor; Res_ohm: 1400; Value_Code: 1k40; Tolerance_%: 1; Power_W: 0.063; Value2: 0.063W; VDC_V: 50; TempCo: 100 ppm/C; EIA_Code: E96; U/M: EA
R208 = CRCW06031M00FKEA: RES, 1.00 M, 1%, 0.1 W, 0603; Manufacturer: Vishay-Dale; CompType: Resistor; Res_ohm: 1000000; Value_Code: 1M00; Tolerance_%: 1; Power_W: 0.1; Value2: 0.1W; VDC_V: 75; TempCo: 100 ppm/C; EIA_Code: E96; U/M: EA
R209 = CRCW0402100RFKED: RES, 100, 1%, 0.063 W, 0402; Manufacturer: Vishay-Dale; CompType: Resistor; Value_Code: 100R; Tolerance_%: 1; Power_W: 0.063; Value2: 0.063W; VDC_V: 50; TempCo: 100 ppm/C; EIA_Code: E96; U/M: EA
S1-S4 = TL1015AF160QG: Switch, Tactile, SPST-NO, 0.05A, 12V, SMT; Manufacturer: E-Switch; SymbolCreator: a0412235; VDC_V: 12; SwitchFunction: Off-Mom; PositionCount: 1; CurrentRating_mA: 50
U2 = MSP430F5529IPN: 25 MHz Mixed Signal Microcontroller with 128 KB Flash, 8192 B SRAM and 63 GPIOs, -40 to 85 degC, 80-pin QFP (PN), Green (RoHS & no Sb/Br); Alternate Manufacturer: Texas Instruments; Alternate PartNumber: Equivalent; ADC: 12-bit SAR; ADC Channels: 16; Brown Out Reset: Yes; DMA: 3; Flash(KB): 128; Frequency(MHz): 25; GPIO: 63; Multiplier: 32x32; Pin/Package: 0DIESALE, 80LQFP; SRAM(B): 8192; SubFamily: 5 Series; Timers - 16-bit: 4; USB: 1; USCI_A (UART/LIN/IrDA/SPI): 2
U200 = 24FC1025T-I/SN: IC, EEPROM, 512kB, 1MHz, SOIC-8; Manufacturer: Microchip; SymbolCreator: a0411947
Y101 = MS3V-T1R 32.768KHZ +/-20PPM 12.5PF: Crystal, 32.768kHz, 12.5pF, SMD; Manufacturer: Micro Crystal AG; SymbolCreator: a0412235; U/M: EA; TaMin_C: -40; TaMax_C: 85; Frequency Stability: ±20ppm
Y102 = 7M-12.000MAAJ-T: Crystal, 12.000MHz, 18pF, SMD; Manufacturer: TXC Corporation; SymbolCreator: a0412235; U/M: EA; TaMin_C: -20; TaMax_C: 70; Frequency Stability: ±30ppm

## Sheet TIDA-00662_ExternalInterfaces.SchDoc: Interfaces
size 431 x 279 mm; Date: Not shown in title block; ApprovedBy: Not shown in title block; CheckedBy: Not shown in title block; Author: Not shown in title block; CompanyName: Not shown in title block; DrawnBy: NewTec; Engineer: Not shown in title block; Organization: Not shown in title block; Address1: Not shown in title block; Address2: Not shown in title block; Address3: Not shown in title block; Address4: Not shown in title block; DocumentNumber: 4; Revision: Use project parameter SCH_Rev; SheetNumber: 4; SheetTotal: 6; PageSetup: Record=PageOptions¦CenterHorizontal=True¦CenterVertical=True¦PrintScale=1.00¦XCorrection=1.00¦YCorrection=1.00¦PrintKind=0¦BorderSize=5000000¦LeftOffset=0¦BottomOffset=0¦Orientation=2¦PaperLength=1000¦PaperWidth=1000¦Scale=100¦PaperSource=15¦PrintQuality=600¦MediaType=1¦DitherType=10¦PaperKind=Letter¦PrintScaleMode=1
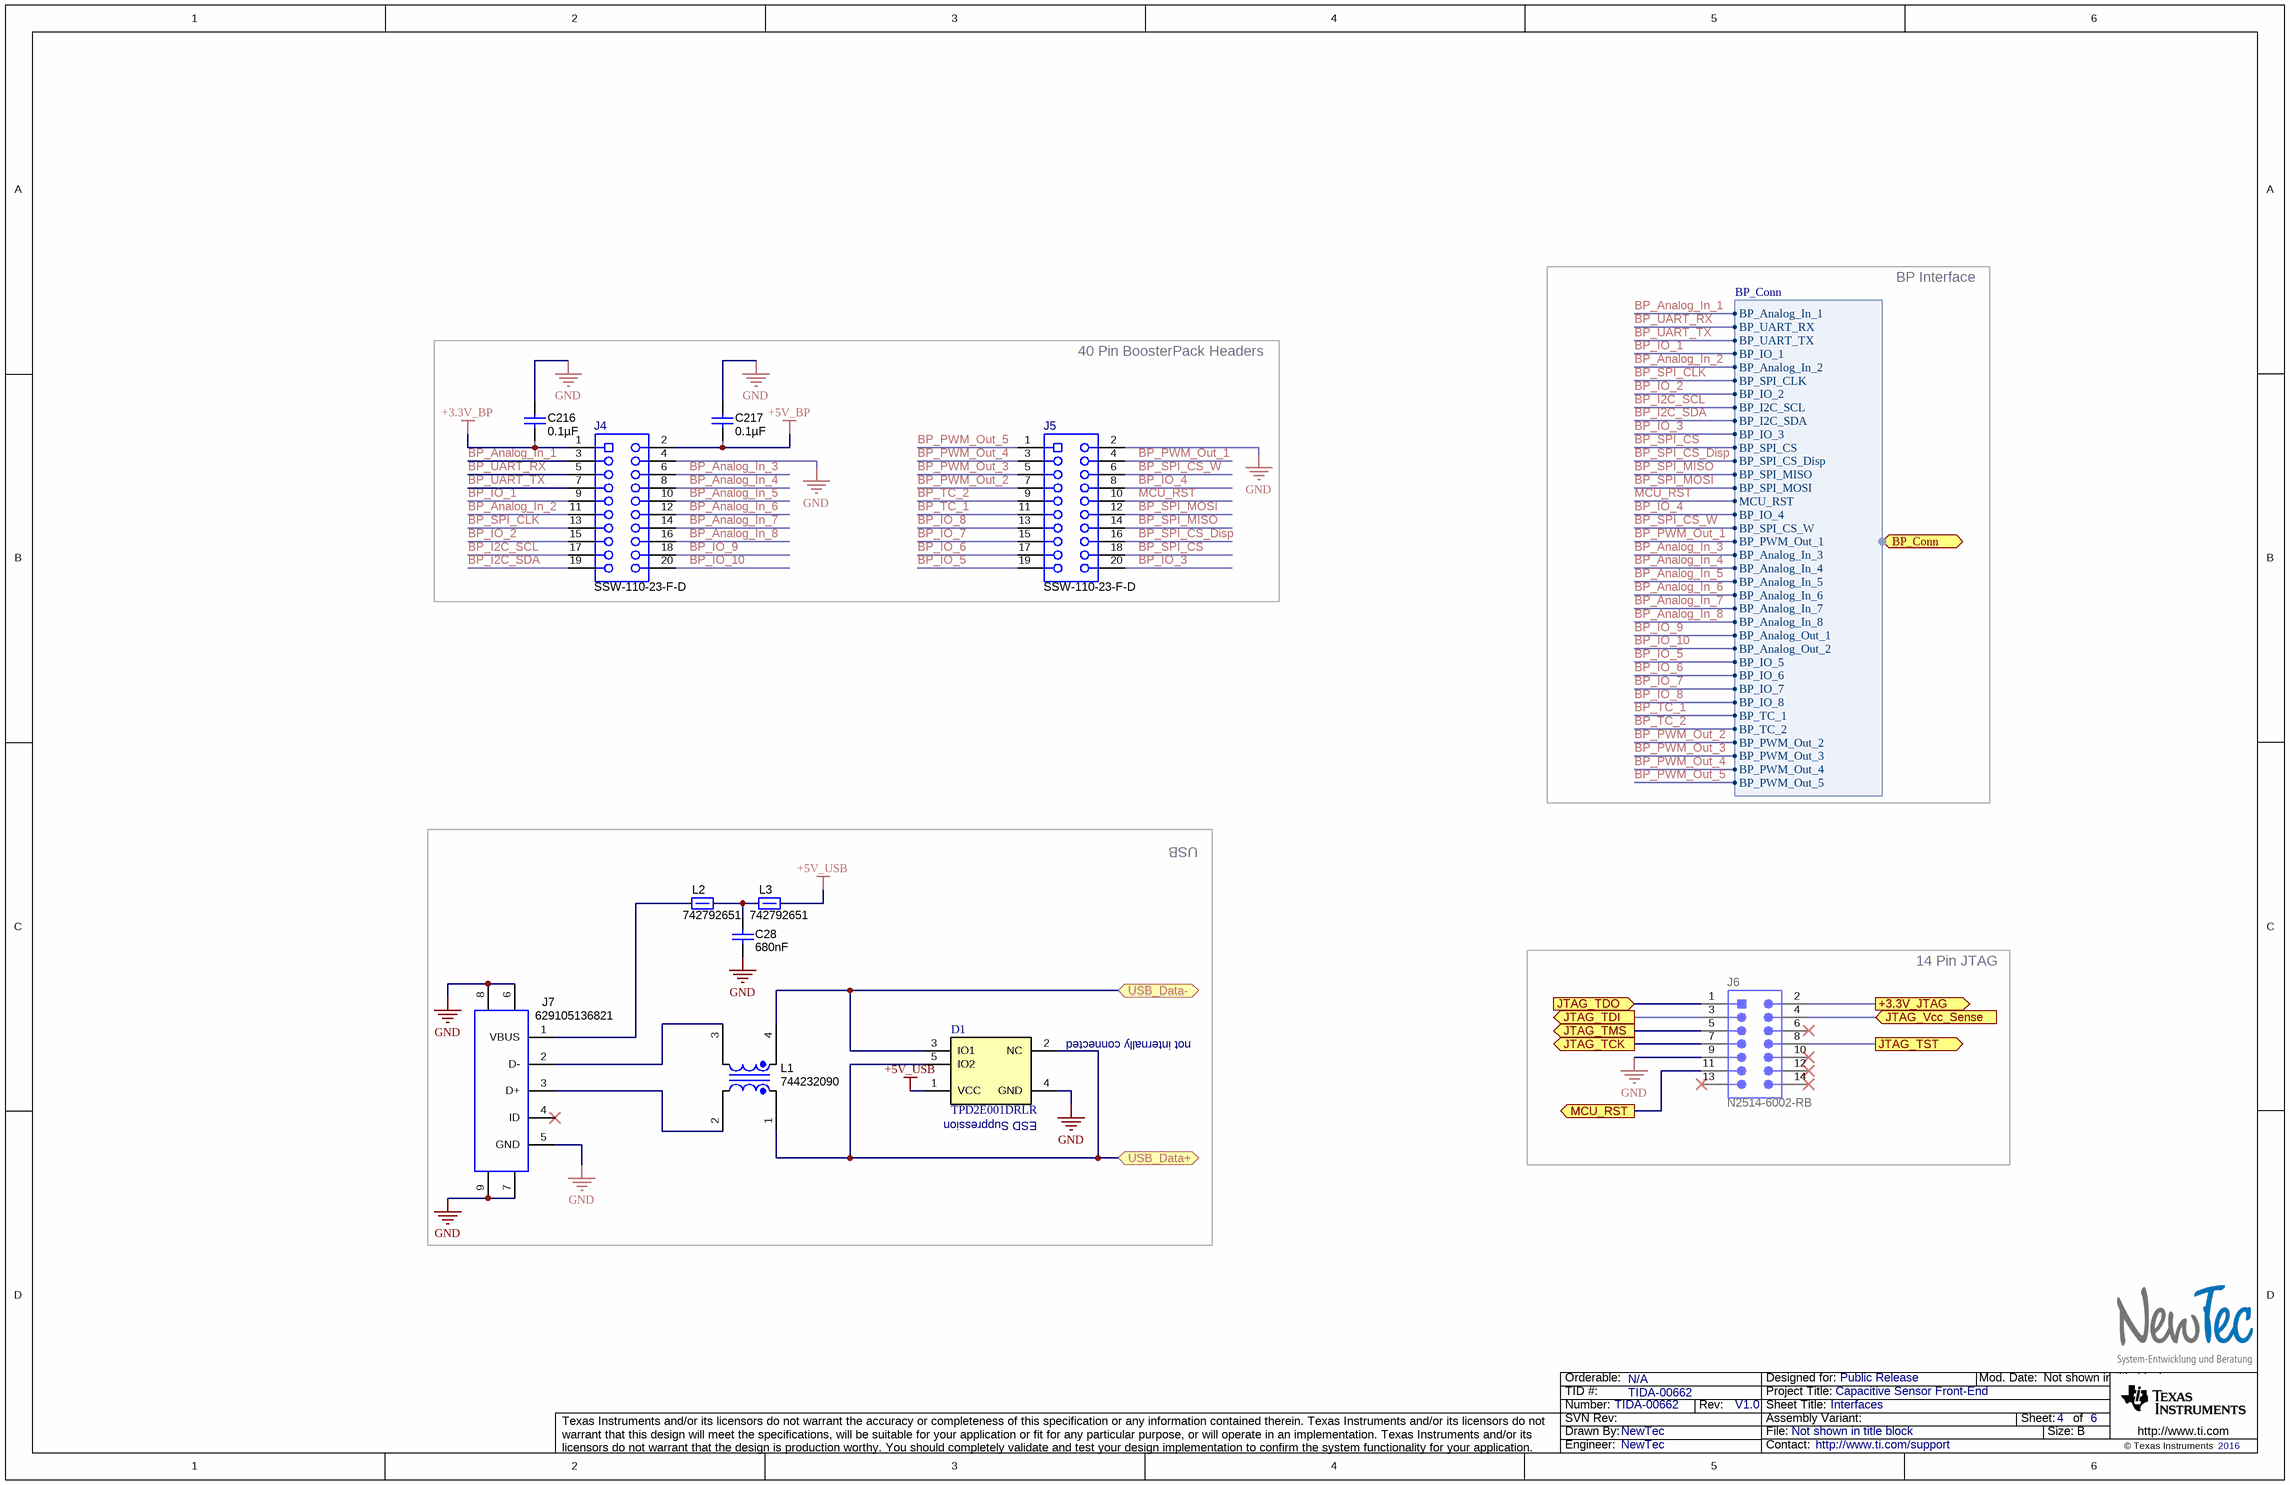
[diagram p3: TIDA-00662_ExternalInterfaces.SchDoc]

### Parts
C28  680nF  [0603_095]
C216  ValueDisplayed: 0.1µF  [0402W]  (hidden comment: 0.1uF)
C217  ValueDisplayed: 0.1µF  [0402W]  (hidden comment: 0.1uF)
D1  TPD2E001DRLR  [DRL0005A]
J4  SSW-110-23-F-D  [CONN_SSW-110-23-F-D]
J5  SSW-110-23-F-D  [CONN_SSW-110-23-F-D]
J6  N2514-6002-RB  [3M_x2514-60xx]
J7  629105136821  [Wurth_629105136821]
L1  744232090  [WE-CNSW_1206]
L2  742792651  [0603]
L3  742792651  [0603]

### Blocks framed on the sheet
40 Pin BoosterPack Headers: C216 C217 J4 J5
USB: C28 D1 J7 L1-L3
14 Pin JTAG: J6

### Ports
+3.3V_JTAG (out), BP_Conn (harness BP_Conn), JTAG_TCK (out), JTAG_TDI (out), JTAG_TDO (in), JTAG_TMS (out), JTAG_TST (out), JTAG_Vcc_Sense (in), MCU_RST (out), USB_Data+ (bidir), USB_Data- (bidir)

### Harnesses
BP_Conn: BP_Analog_In_1, BP_UART_RX, BP_UART_TX, BP_IO_1, BP_Analog_In_2, BP_SPI_CLK, BP_IO_2, BP_I2C_SCL, BP_I2C_SDA, BP_IO_3, BP_SPI_CS, BP_SPI_CS_Disp, BP_SPI_MISO, BP_SPI_MOSI, MCU_RST, BP_IO_4, BP_SPI_CS_W, BP_PWM_Out_1, BP_Analog_In_3, BP_Analog_In_4, BP_Analog_In_5, BP_Analog_In_6, BP_Analog_In_7, BP_Analog_In_8, BP_Analog_Out_1, BP_Analog_Out_2, BP_IO_5, BP_IO_6, BP_IO_7, BP_IO_8, BP_TC_1, BP_TC_2, BP_PWM_Out_2, BP_PWM_Out_3, BP_PWM_Out_4, BP_PWM_Out_5

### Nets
+3.3V_BP: C216.2 J4.1
+5V_BP: C217.2 J4.2
+5V_USB: D1.1(VCC) L3.2
GND: C28.1 C216.1 C217.1 D1.4(GND) J4.4 J5.2 J6.9 J7.5(GND) J7.6 J7.7 J7.8 J7.9
+3.3V_JTAG: J6.2 ; port +3.3V_JTAG
BP_Analog_In_1: J4.3 ; port BP_Conn.BP_Analog_In_1
BP_Analog_In_2: J4.11 ; port BP_Conn.BP_Analog_In_2
BP_Analog_In_3: J4.6 ; port BP_Conn.BP_Analog_In_3
BP_Analog_In_4: J4.8 ; port BP_Conn.BP_Analog_In_4
BP_Analog_In_5: J4.10 ; port BP_Conn.BP_Analog_In_5
BP_Analog_In_6: J4.12 ; port BP_Conn.BP_Analog_In_6
BP_Analog_In_7: J4.14 ; port BP_Conn.BP_Analog_In_7
BP_Analog_In_8: J4.16 ; port BP_Conn.BP_Analog_In_8
BP_I2C_SCL: J4.17 ; port BP_Conn.BP_I2C_SCL
BP_I2C_SDA: J4.19 ; port BP_Conn.BP_I2C_SDA
BP_IO_1: J4.9 ; port BP_Conn.BP_IO_1
BP_IO_2: J4.15 ; port BP_Conn.BP_IO_2
BP_IO_3: J5.20 ; port BP_Conn.BP_IO_3
BP_IO_4: J5.8 ; port BP_Conn.BP_IO_4
BP_IO_5: J5.19 ; port BP_Conn.BP_IO_5
BP_IO_6: J5.17 ; port BP_Conn.BP_IO_6
BP_IO_7: J5.15 ; port BP_Conn.BP_IO_7
BP_IO_8: J5.13 ; port BP_Conn.BP_IO_8
BP_IO_9: J4.18 ; port BP_Conn.BP_Analog_Out_1
BP_IO_10: J4.20 ; port BP_Conn.BP_Analog_Out_2
BP_PWM_Out_1: J5.4 ; port BP_Conn.BP_PWM_Out_1
BP_PWM_Out_2: J5.7 ; port BP_Conn.BP_PWM_Out_2
BP_PWM_Out_3: J5.5 ; port BP_Conn.BP_PWM_Out_3
BP_PWM_Out_4: J5.3 ; port BP_Conn.BP_PWM_Out_4
BP_PWM_Out_5: J5.1 ; port BP_Conn.BP_PWM_Out_5
BP_SPI_CLK: J4.13 ; port BP_Conn.BP_SPI_CLK
BP_SPI_CS: J5.18 ; port BP_Conn.BP_SPI_CS
BP_SPI_CS_Disp: J5.16 ; port BP_Conn.BP_SPI_CS_Disp
BP_SPI_CS_W: J5.6 ; port BP_Conn.BP_SPI_CS_W
BP_SPI_MISO: J5.14 ; port BP_Conn.BP_SPI_MISO
BP_SPI_MOSI: J5.12 ; port BP_Conn.BP_SPI_MOSI
BP_TC_1: J5.11 ; port BP_Conn.BP_TC_1
BP_TC_2: J5.9 ; port BP_Conn.BP_TC_2
BP_UART_RX: J4.5 ; port BP_Conn.BP_UART_RX
BP_UART_TX: J4.7 ; port BP_Conn.BP_UART_TX
JTAG_TCK: J6.7 ; port JTAG_TCK
JTAG_TDI: J6.3 ; port JTAG_TDI
JTAG_TDO: J6.1 ; port JTAG_TDO
JTAG_TMS: J6.5 ; port JTAG_TMS
JTAG_TST: J6.8 ; port JTAG_TST
JTAG_Vcc_Sense: J6.4 ; port JTAG_Vcc_Sense
MCU_RST: J5.10 J6.11 ; port MCU_RST, port BP_Conn.MCU_RST
USB_Data+: D1.2(NC) D1.5(IO2) L1.1 ; port USB_Data+
USB_Data-: D1.3(IO1) L1.4 ; port USB_Data-
NetC28_2: C28.2 L2.2 L3.1
NetJ7_1: J7.1(VBUS) L2.1
NetJ7_2: J7.2(D-) L1.3
NetJ7_3: J7.3(D+) L1.2

Not connected (* = marked no-connect by the designer): J6 6* 10* 12* 13* 14*; J7 4(ID)*

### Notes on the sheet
- BP Interface
- (near D1) not internally connected
- (near D1) ESD Suppression

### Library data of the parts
C28 = 885012206051: CAP, CERM, 680 nF, 16V, +/- 10%, X7R, 0603_095; Manufacturer: Wurth Elektronik; Polarized: N; CompType: Capacitor; U/M: EA; Cap_F: 0.000000680; Tolerance_%: 10; Value1: Unknown; VDC_V: 16; TaMin_C: -55; TaMax_C: 125; Cap_Case: 0603
C216 C217 = 885012205037: as C100 on sheet TIDA-00662_AIC3254
D1 = TPD2E001DRLR: Low-Capacitance + / - 15 kV ESD-Protection Array for High-Speed Data Interfaces, 2 Channels, -40 to +85 degC, 5-pin SOT (DRL), Green (RoHS & no Sb/Br); Manufacturer: Texas Instruments; Alternate PartNumber: Equivalent; Breakdown Voltage(Min)(V): 11; IEC 61000-4-2 Air-Gap(+/- kV): 15; IEC 61000-4-2 Contact(+/- kV): 8; IO Capacitance(Typ)(pF): 1.5; IO Leakage Current(nA): 1; SubFamily: ESD Solution; USB High Speed: TRUE
J4 J5 = SSW-110-23-F-D: Connector, Receptacle, 100mil, 10x2, Gold plated, TH; Manufacturer: Samtec; SymbolCreator: a0412235; U/M: EA
J6 = N2514-6002-RB: Header (shrouded), 100mil, 7x2, Gold, TH; Manufacturer: 3M; SymbolCreator: a0412235; U/M: EA
J7 = 629105136821: USB 2.0 TYPE B, R/A, SMT; Manufacturer: Wurth Elektronik; SymbolCreator: a0799628; CompType: Receptacle; Gender: Female; ContactFinish: Gold; Current_A: 1.8; Voltage_V: 30; Cert_UL: Y
L1 = 744232090: Coupled inductor,  A, 0.3 ohm, +/- 25%, SMD; Manufacturer: Wurth Elektronik; SymbolCreator: a0412235; DCR_ohm: 0.3; Tolerance_%: 25
L2 L3 = 742792651: Ferrite Bead, 600 ohm @ 100 MHz, 1 A, 0603; Manufacturer: Wurth Elektronik; Value: 600 ohm; Imax_A: 1; DCR_ohm: 0.2; Value1: 0.2 ohm; Value2: 1A; ZTyp@100MHz_Ohm: 600

## Sheet TIDA-00662_PowerSupply.SchDoc: Power Supply
size 431 x 279 mm; Date: Not shown in title block; ApprovedBy: Not shown in title block; CheckedBy: Not shown in title block; Author: Not shown in title block; CompanyName: Not shown in title block; DrawnBy: NewTec; Engineer: Not shown in title block; Organization: Not shown in title block; Address1: Not shown in title block; Address2: Not shown in title block; Address3: Not shown in title block; Address4: Not shown in title block; DocumentNumber: 5; Revision: Use project parameter SCH_Rev; SheetNumber: 5; SheetTotal: 6; PageSetup: Record=PageOptions¦CenterHorizontal=True¦CenterVertical=True¦PrintScale=1.00¦XCorrection=1.00¦YCorrection=1.00¦PrintKind=0¦BorderSize=5000000¦LeftOffset=0¦BottomOffset=0¦Orientation=2¦PaperLength=1000¦PaperWidth=1000¦Scale=100¦PaperSource=15¦PrintQuality=600¦MediaType=1¦DitherType=10¦PaperKind=Letter¦PrintScaleMode=1
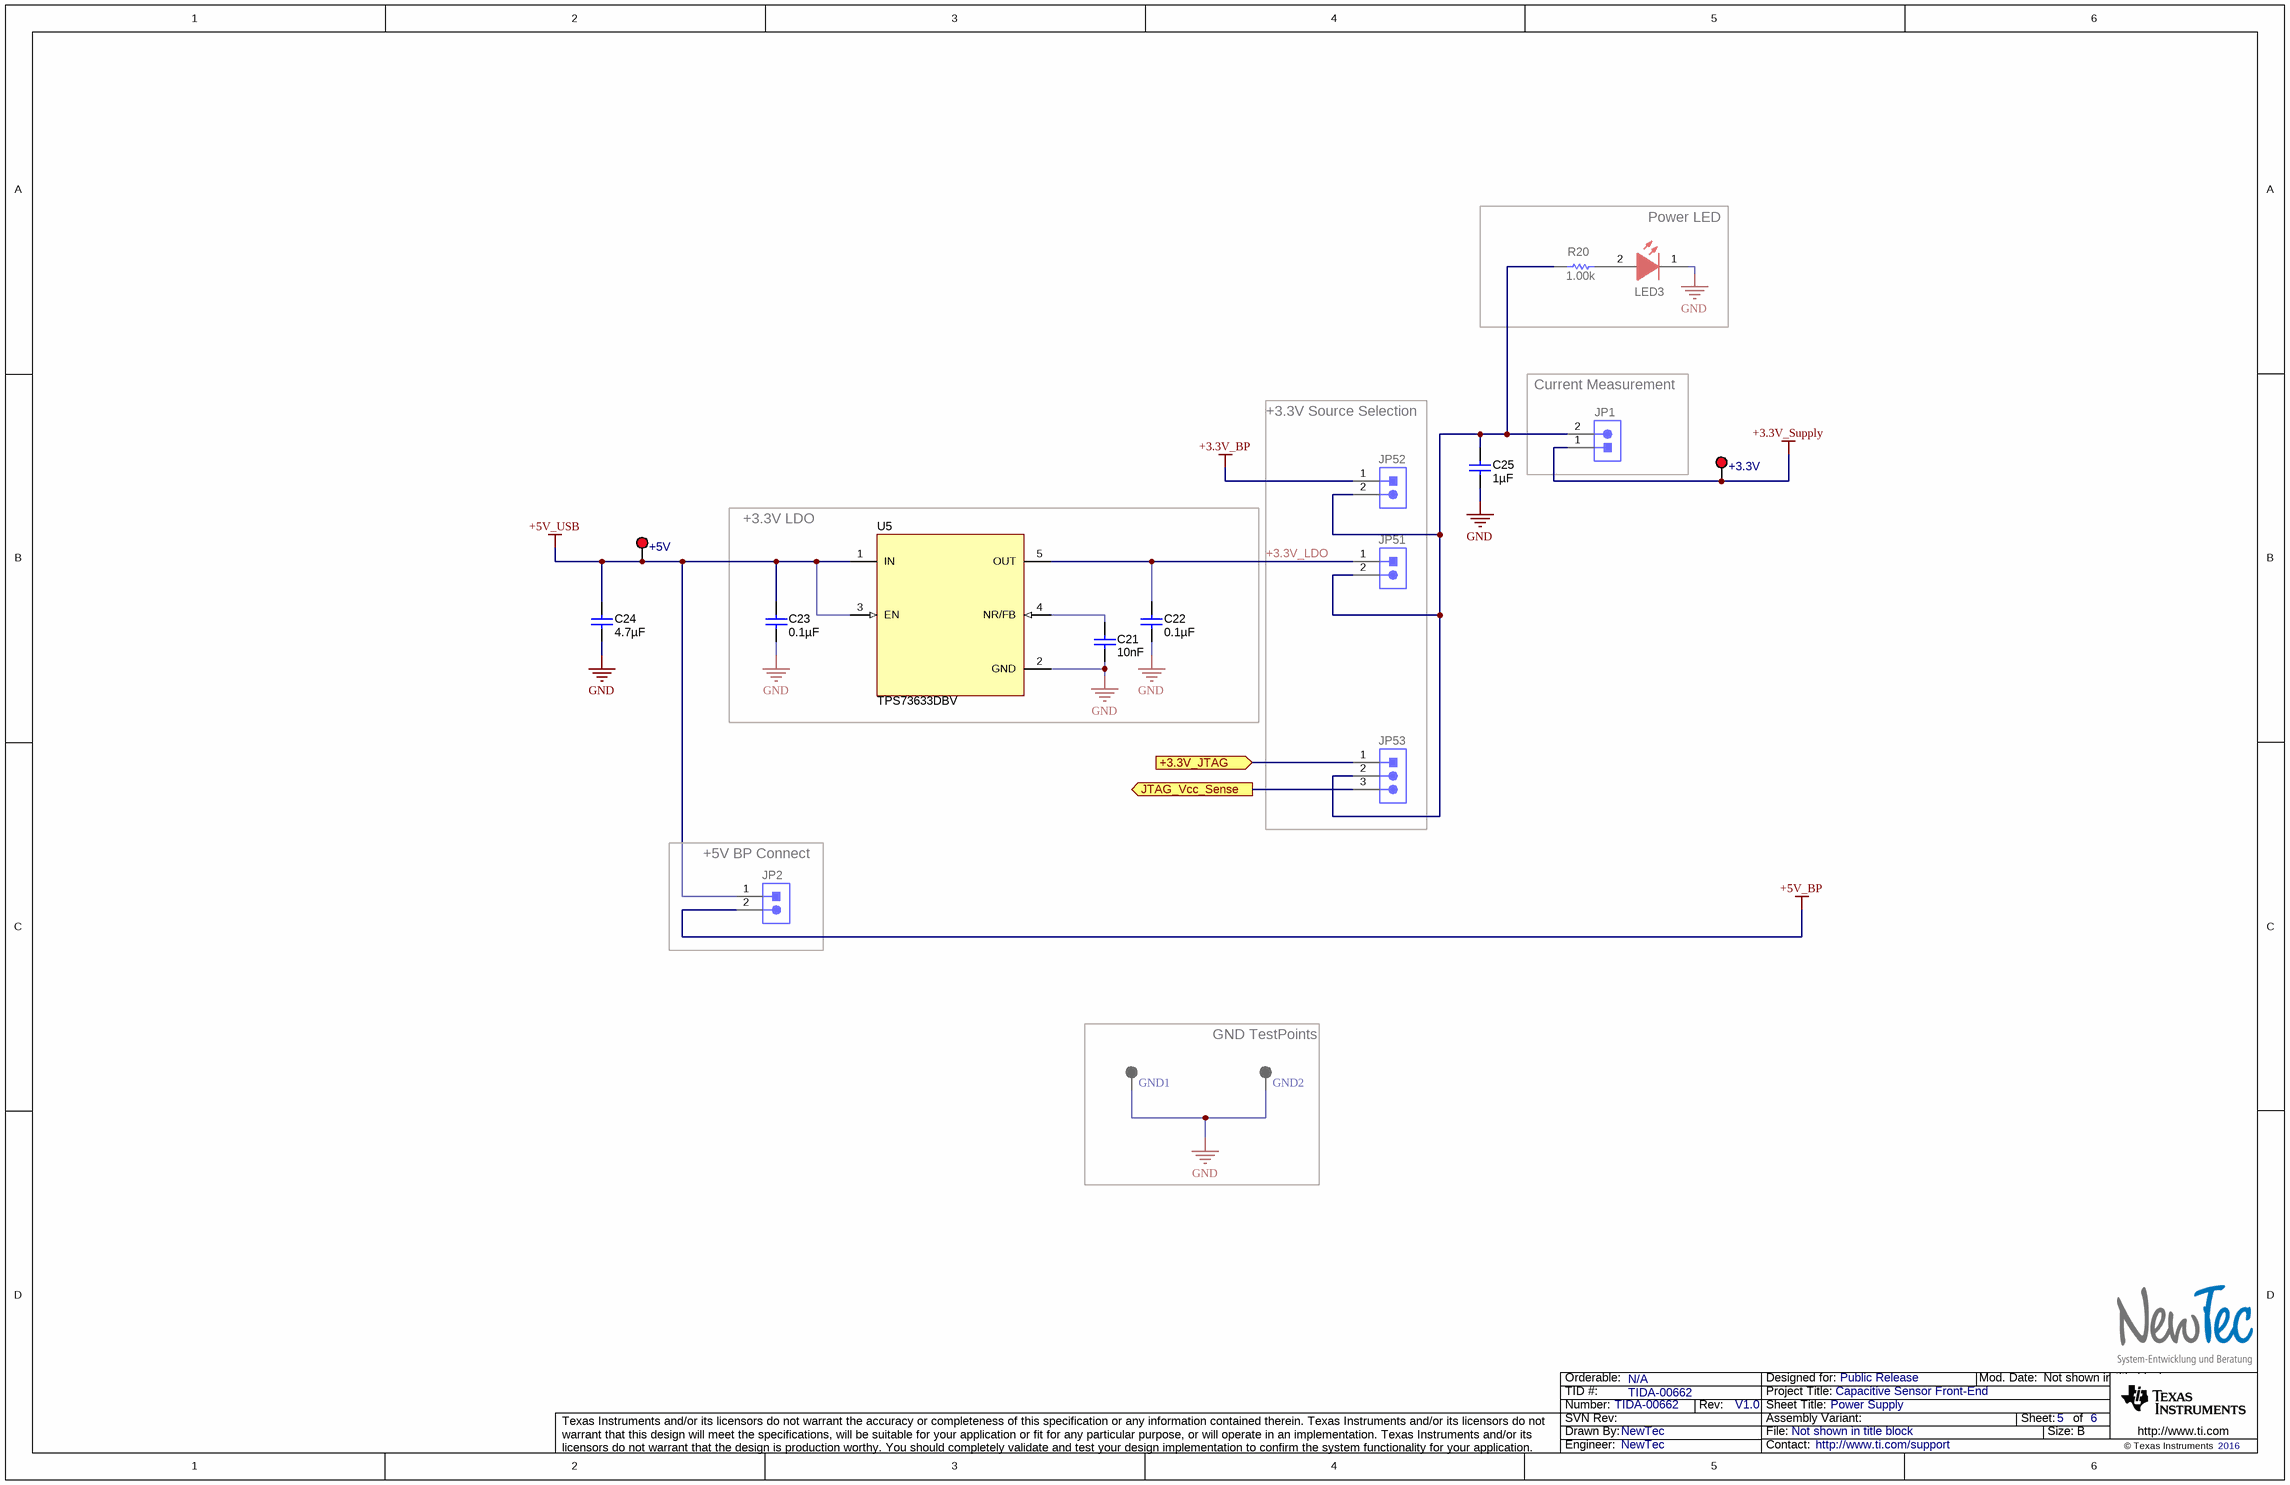
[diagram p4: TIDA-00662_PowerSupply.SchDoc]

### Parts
+3.3V  5000  [Keystone5000]  (value not drawn)
+5V  5000  [Keystone5000]  (value not drawn)
C21  10nF  [0402W]
C22  ValueDisplayed: 0.1µF  [0603_095]  (hidden comment: 0.1uF)
C23  ValueDisplayed: 0.1µF  [0603_095]  (hidden comment: 0.1uF)
C24  ValueDisplayed: 4.7µF  [0805_145]  (hidden comment: 4.7uF)
C25  ValueDisplayed: 1µF  [0603_095]  (hidden comment: 0.1uF)
GND1  5011  [Keystone5011]  (value not drawn)
GND2  5011  [Keystone5011]  (value not drawn)
JP1  61300211121  [WURTH_61300211121]  (value not drawn)
JP2  61300211121  [WURTH_61300211121]  (value not drawn)
JP51  61300211121  [WURTH_61300211121]  (value not drawn)
JP52  61300211121  [WURTH_61300211121]  (value not drawn)
JP53  61300311121  [WURTH_61300311121]  (value not drawn)
LED3  150120RS75000  [WL_SMCW_RED_1206]  (value not drawn)
R20  1.00k  [0402W]
U5  TPS73633DBV  [DBV0005A_N]

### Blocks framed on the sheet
Power LED: LED3 R20
Current Measurement: JP1
+3.3V Source Selection: JP51-JP53
+3.3V LDO: C21-C23 U5
+5V BP Connect: JP2
GND TestPoints: GND1 GND2

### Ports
+3.3V_JTAG (in), JTAG_Vcc_Sense (out)

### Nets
+3.3V_BP: JP52.1
+3.3V_Supply: +3.3V.1 JP1.1
+5V_BP: JP2.2
+5V_USB: +5V.1 C23.2 C24.1 JP2.1 U5.1(IN) U5.3(EN)
GND: C21.2 C22.1 C23.1 C24.2 C25.1 GND1.1 GND2.1 LED3.1(K) U5.2(GND)
+3.3V_JTAG: JP53.1 ; port +3.3V_JTAG
+3.3V_LDO: C22.2 JP51.1 U5.5(OUT)
JTAG_Vcc_Sense: JP53.3 ; port JTAG_Vcc_Sense
NetC21_1: C21.1 U5.4(NR/FB)
NetC25_2: C25.2 JP1.2 JP51.2 JP52.2 JP53.2 R20.1
NetLED3_2: LED3.2(A) R20.2

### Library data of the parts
+3.3V +5V = 5000: Test Point, Miniature, Red, TH; Manufacturer: Keystone; CompType: Test Point Loop; U/M: EA
C21 = 885012205031: CAP, CERM, 0.01 µF, 16 V, +/- 10%, X7R, 0402; Manufacturer: Wurth Elektronik; Polarized: N; CompType: Capacitor; U/M: EA; Cap_F: 0.00000001; Tolerance_%: 10; Value1: Unknown; VDC_V: 16; Value2: 16V; TaMin_C: -55; TaMax_C: 125; Cap_Case: 0402
C22 C23 C25 = 885012206046: CAP, CERM, 0.1 µF, 16 V, +/- 10%, X7R, 0603_095; Manufacturer: Wurth Elektronik; Polarized: N; CompType: Capacitor; U/M: EA; Cap_F: 0.0000001; Tolerance_%: 10; Value1: Unknown; VDC_V: 16; Value2: 16V; TaMin_C: -55; TaMax_C: 125; Cap_Case: 0603
C24 = 885012207025: as C215 on sheet TIDA-00662_MCU
GND1 GND2 = 5011: Test Point, Multipurpose, Black, TH; Manufacturer: Keystone; CompType: Test Point Loop; U/M: EA
JP1 JP2 JP51 JP52 = 61300211121: as JP11 on sheet TIDA-00662_AIC3254
JP53 = 61300311121: as JP31 on sheet TIDA-00662_AIC3254
LED3 = 150120RS75000: as LED1 on sheet TIDA-00662_MCU
R20 = CRCW04021K00FKED: as R203 on sheet TIDA-00662_MCU
U5 = TPS73633DBV: Cap-Free, NMOS, 400mA Low-Dropout Regulator with Reverse Current Protection, DBV0005A; Manufacturer: Texas Instruments; SymbolCreator: a0411947; CompType: IC; U/M: EA

## Sheet TIDA-00662_TID_Hardware.SchDoc: Hardware
size 431 x 279 mm; Date: Not shown in title block; ApprovedBy: Not shown in title block; CheckedBy: Not shown in title block; Author: Not shown in title block; CompanyName: Not shown in title block; DrawnBy: NewTec; Engineer: Not shown in title block; Organization: Not shown in title block; Address1: Not shown in title block; Address2: Not shown in title block; Address3: Not shown in title block; Address4: Not shown in title block; DocumentNumber: 6; Revision: Use project parameter SCH_Rev; SheetNumber: 6; SheetTotal: 6; PageSetup: Record=PageOptions¦CenterHorizontal=True¦CenterVertical=True¦PrintScale=1.00¦XCorrection=1.00¦YCorrection=1.00¦PrintKind=0¦BorderSize=5000000¦LeftOffset=0¦BottomOffset=0¦Orientation=2¦PaperLength=1000¦PaperWidth=1000¦Scale=100¦PaperSource=15¦PrintQuality=600¦MediaType=1¦DitherType=10¦PaperKind=Letter¦PrintScaleMode=1
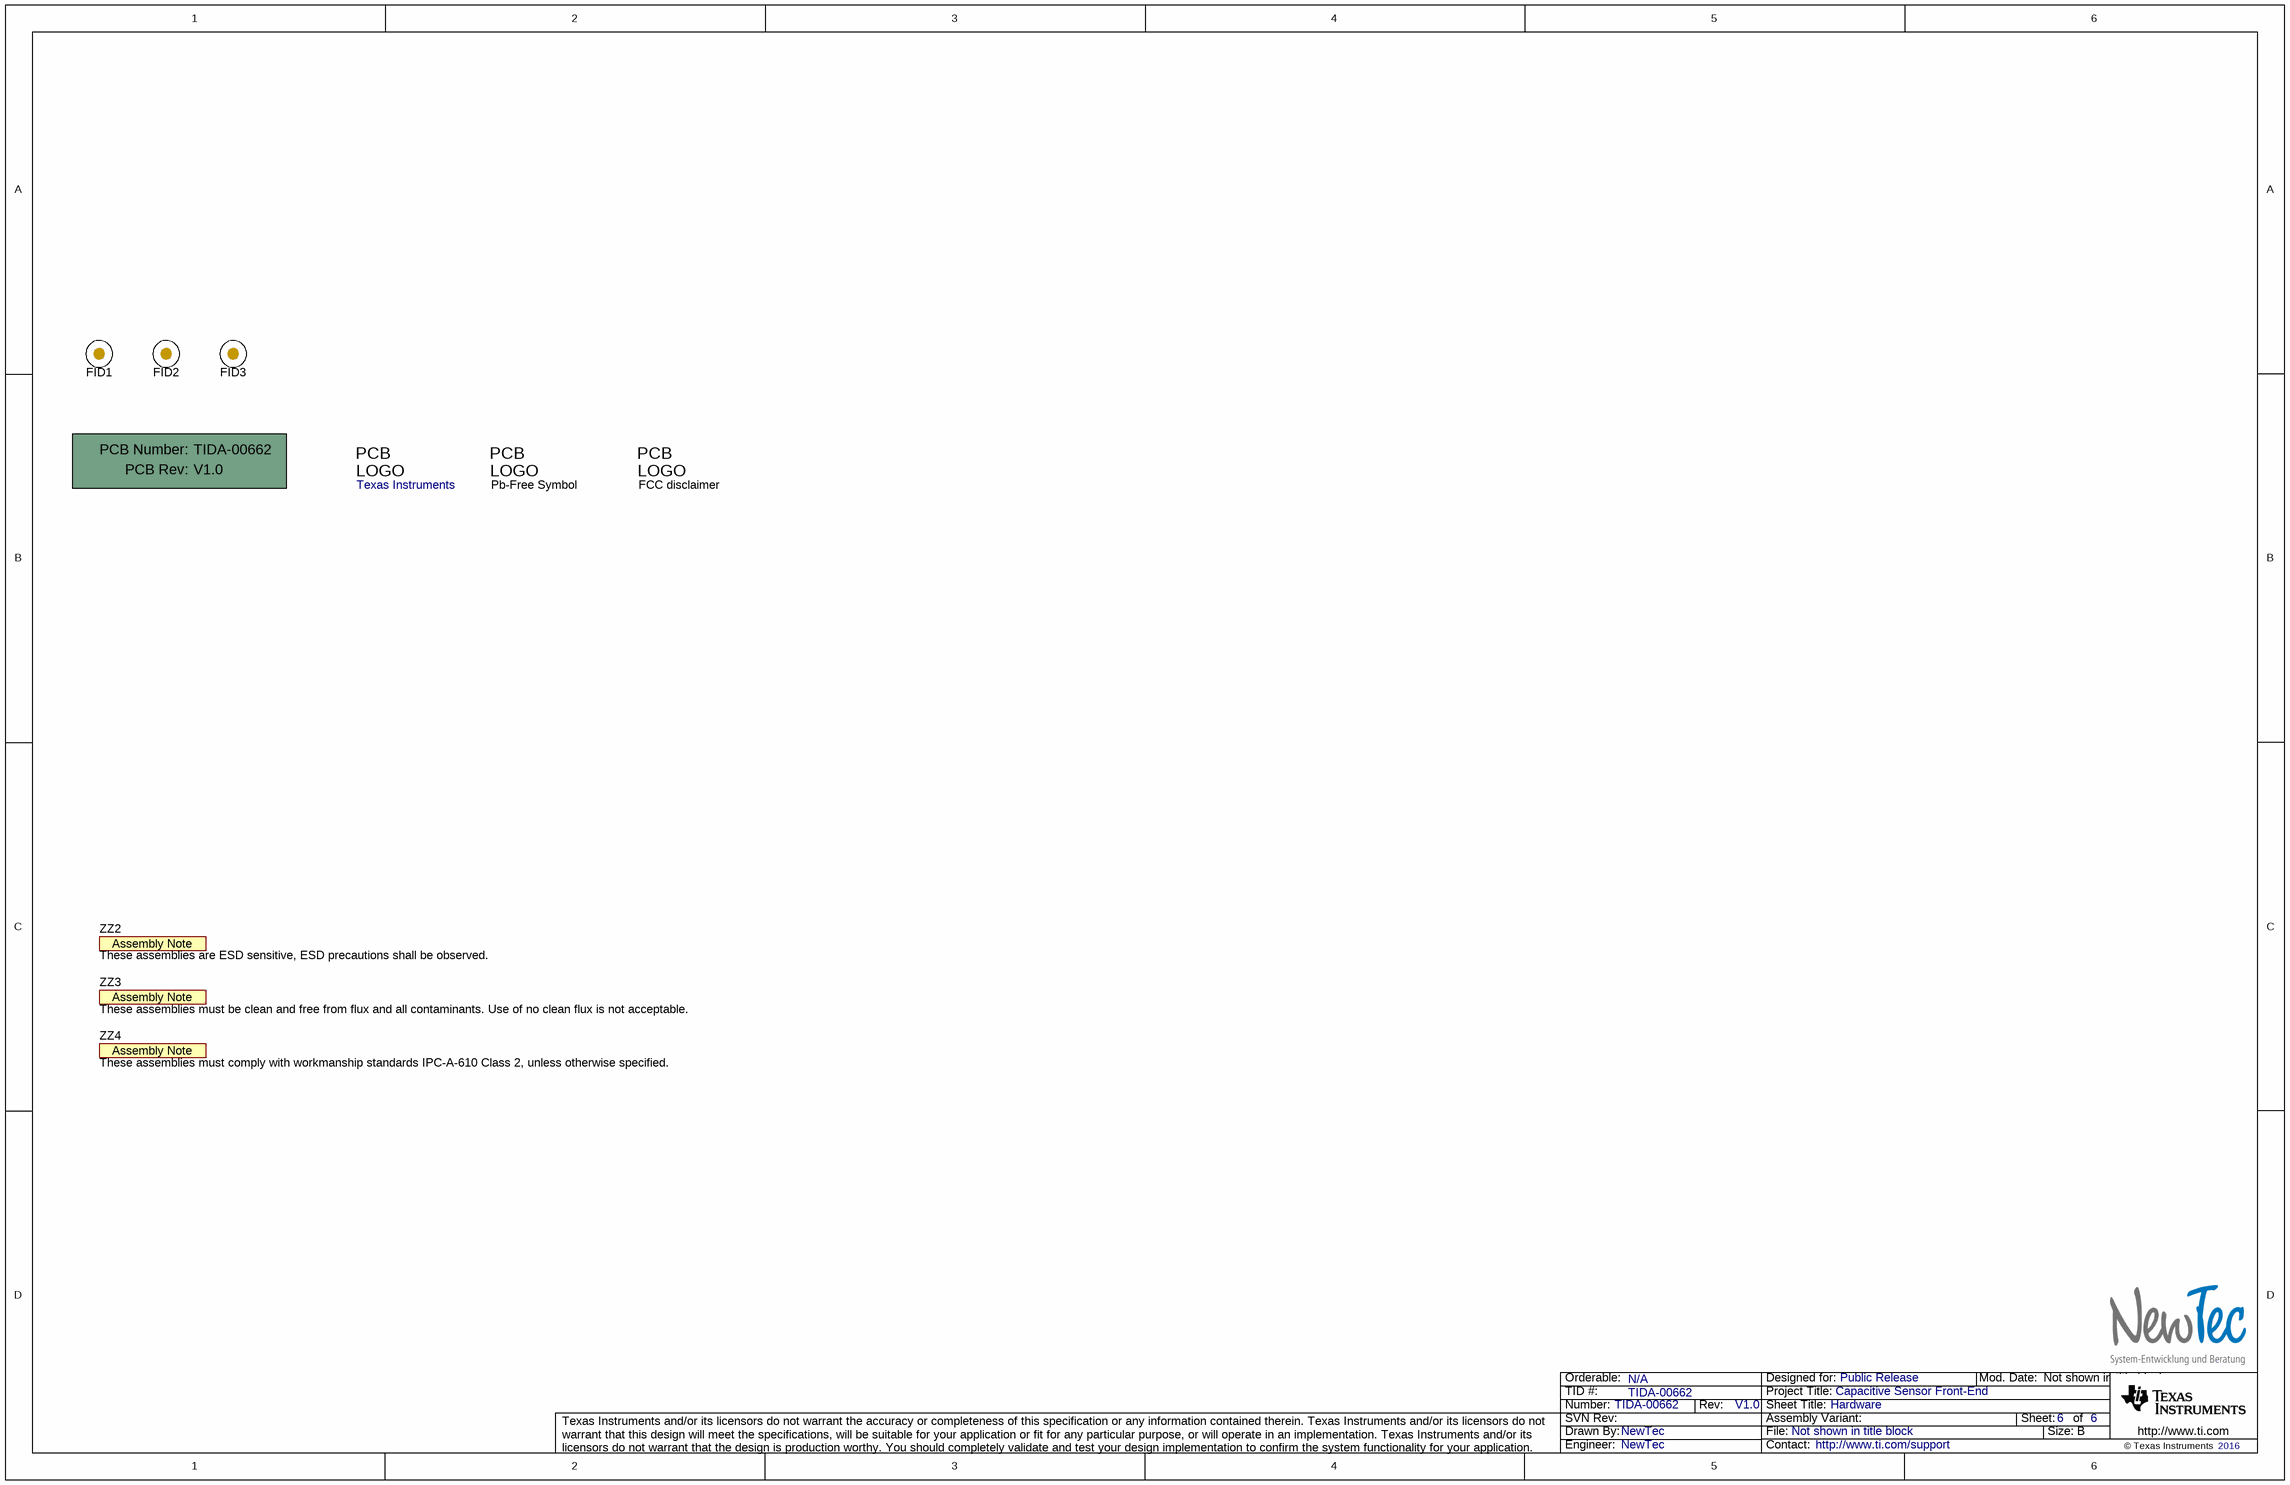
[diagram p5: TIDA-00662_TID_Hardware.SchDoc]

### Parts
!PCB  Printed Circuit Board  (value not drawn)  (mechanical)
FID1  Fiducial  [Fiducial10-20]  (value not drawn)
FID2  Fiducial  [Fiducial10-20]  (value not drawn)
FID3  Fiducial  [Fiducial10-20]  (value not drawn)
Logo2  Pb-Free Symbol  [Pb-Free_Overlay_Small]  (no BOM)
Logo3  FCC disclaimer  [FCC_disclaimer]  (no BOM)
Logo4  Texas Instruments  [TI_Stacked_Overlay_Small_Vertical]  (no BOM)
ZZ2  These assemblies are ESD sensitive, ESD precautions shall be observed.  [AssemblyNote]  (no BOM)
ZZ3  These assemblies must be clean and free from flux and all contaminants. Use of no clean flux is not acceptable.  [AssemblyNote]  (no BOM)
ZZ4  These assemblies must comply with workmanship standards IPC-A-610 Class 2, unless otherwise specified.  [AssemblyNote]  (no BOM)

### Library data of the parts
!PCB = PCB: Manufacturer: Any; PartNumber: TIDA-00662; SymbolCreator: a0412235
FID1-FID3 = Fiducial: Fiducial mark.  There is nothing to buy or mount.; SymbolCreator: codlsc
Logo2 = Pb-Free: SymbolCreator: a0412235
Logo3 = FCC_disclaimer: SymbolCreator: codlsc
Logo4 = TI_Logo: Texas Instrument Corporate Signature; SymbolCreator: a0412235
ZZ2-ZZ4 = AssemblyNote: SymbolCreator: codlsc

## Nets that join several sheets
+3.3V_BP: TIDA-00662_ExternalInterfaces (C216.2 J4.1), TIDA-00662_PowerSupply (JP52.1)
+3.3V_Supply: TIDA-00662_AIC3254 (14 pins), TIDA-00662_MCU (14 pins), TIDA-00662_PowerSupply (+3.3V.1 JP1.1)
+5V_BP: TIDA-00662_ExternalInterfaces (C217.2 J4.2), TIDA-00662_PowerSupply (JP2.2)
+5V_USB: TIDA-00662_MCU (C212.2 U2.65), TIDA-00662_ExternalInterfaces (D1.1 L3.2), TIDA-00662_PowerSupply (6 pins)
GND: TIDA-00662_AIC3254 (25 pins), TIDA-00662_MCU (33 pins), TIDA-00662_ExternalInterfaces (12 pins), TIDA-00662_PowerSupply (9 pins)
+3.3V_JTAG: TIDA-00662_ExternalInterfaces (J6.2), TIDA-00662_PowerSupply (JP53.1)
BP_Analog_In_1: TIDA-00662_MCU (U2.2), TIDA-00662_ExternalInterfaces (J4.3)
BP_Analog_In_2: TIDA-00662_MCU (U2.3), TIDA-00662_ExternalInterfaces (J4.11)
BP_Analog_In_3: TIDA-00662_MCU (U2.77), TIDA-00662_ExternalInterfaces (J4.6)
BP_Analog_In_4: TIDA-00662_MCU (U2.78), TIDA-00662_ExternalInterfaces (J4.8)
BP_Analog_In_5: TIDA-00662_MCU (U2.79), TIDA-00662_ExternalInterfaces (J4.10)
BP_Analog_In_6: TIDA-00662_MCU (U2.80), TIDA-00662_ExternalInterfaces (J4.12)
BP_Analog_In_7: TIDA-00662_MCU (U2.1), TIDA-00662_ExternalInterfaces (J4.14)
BP_Analog_In_8: TIDA-00662_MCU (U2.4), TIDA-00662_ExternalInterfaces (J4.16)
BP_I2C_SCL: TIDA-00662_MCU (U2.47), TIDA-00662_ExternalInterfaces (J4.17)
BP_I2C_SDA: TIDA-00662_MCU (U2.46), TIDA-00662_ExternalInterfaces (J4.19)
BP_IO_1: TIDA-00662_MCU (U2.27), TIDA-00662_ExternalInterfaces (J4.9)
BP_IO_2: TIDA-00662_MCU (U2.25), TIDA-00662_ExternalInterfaces (J4.15)
BP_IO_3: TIDA-00662_MCU (U2.16), TIDA-00662_ExternalInterfaces (J5.20)
BP_IO_4: TIDA-00662_MCU (U2.55), TIDA-00662_ExternalInterfaces (J5.8)
BP_IO_5: TIDA-00662_MCU (U2.17), TIDA-00662_ExternalInterfaces (J5.19)
BP_IO_6: TIDA-00662_MCU (U2.42), TIDA-00662_ExternalInterfaces (J5.17)
BP_IO_7: TIDA-00662_MCU (U2.43), TIDA-00662_ExternalInterfaces (J5.15)
BP_IO_8: TIDA-00662_MCU (U2.44), TIDA-00662_ExternalInterfaces (J5.13)
BP_IO_9: TIDA-00662_MCU (U2.23), TIDA-00662_ExternalInterfaces (J4.18)
BP_IO_10: TIDA-00662_MCU (U2.24), TIDA-00662_ExternalInterfaces (J4.20)
BP_PWM_Out_1: TIDA-00662_MCU (U2.29), TIDA-00662_ExternalInterfaces (J5.4)
BP_PWM_Out_2: TIDA-00662_MCU (U2.56), TIDA-00662_ExternalInterfaces (J5.7)
BP_PWM_Out_3: TIDA-00662_MCU (U2.57), TIDA-00662_ExternalInterfaces (J5.5)
BP_PWM_Out_4: TIDA-00662_MCU (U2.58), TIDA-00662_ExternalInterfaces (J5.3)
BP_PWM_Out_5: TIDA-00662_MCU (U2.59), TIDA-00662_ExternalInterfaces (J5.1)
BP_SPI_CLK: TIDA-00662_MCU (U2.45), TIDA-00662_ExternalInterfaces (J4.13)
BP_SPI_CS: TIDA-00662_MCU (U2.48), TIDA-00662_ExternalInterfaces (J5.18)
BP_SPI_CS_Disp: TIDA-00662_MCU (U2.35), TIDA-00662_ExternalInterfaces (J5.16)
BP_SPI_CS_W: TIDA-00662_MCU (U2.31), TIDA-00662_ExternalInterfaces (J5.6)
BP_SPI_MISO: TIDA-00662_MCU (U2.52), TIDA-00662_ExternalInterfaces (J5.14)
BP_SPI_MOSI: TIDA-00662_MCU (U2.51), TIDA-00662_ExternalInterfaces (J5.12)
BP_TC_1: TIDA-00662_MCU (U2.33), TIDA-00662_ExternalInterfaces (J5.11)
BP_TC_2: TIDA-00662_MCU (U2.34), TIDA-00662_ExternalInterfaces (J5.9)
BP_UART_RX: TIDA-00662_MCU (U2.53), TIDA-00662_ExternalInterfaces (J4.5)
BP_UART_TX: TIDA-00662_MCU (U2.54), TIDA-00662_ExternalInterfaces (J4.7)
DSP_MCU_IO_1: TIDA-00662_AIC3254 (IO1.1 U1.32), TIDA-00662_MCU (U2.21)
DSP_MCU_RST~: TIDA-00662_AIC3254 (U1.31), TIDA-00662_MCU (U2.28)
JTAG_TCK: TIDA-00662_MCU (U2.75), TIDA-00662_ExternalInterfaces (J6.7)
JTAG_TDI: TIDA-00662_MCU (U2.73), TIDA-00662_ExternalInterfaces (J6.3)
JTAG_TDO: TIDA-00662_MCU (U2.72), TIDA-00662_ExternalInterfaces (J6.1)
JTAG_TMS: TIDA-00662_MCU (U2.74), TIDA-00662_ExternalInterfaces (J6.5)
JTAG_TST: TIDA-00662_MCU (U2.71), TIDA-00662_ExternalInterfaces (J6.8)
JTAG_Vcc_Sense: TIDA-00662_ExternalInterfaces (J6.4), TIDA-00662_PowerSupply (JP53.3)
MCU_MCLK: TIDA-00662_AIC3254 (MCLK.1 U1.1), TIDA-00662_MCU (U2.60)
MCU_RST: TIDA-00662_MCU (C205.1 R202.1 S3.1 U2.76), TIDA-00662_ExternalInterfaces (J5.10 J6.11)
MCU_SCL: TIDA-00662_AIC3254 (JP61.3), TIDA-00662_MCU (R201.1 U2.38 U200.6)
MCU_SDA: TIDA-00662_AIC3254 (JP62.3), TIDA-00662_MCU (R200.1 U2.37 U200.5)
SPI_MISO: TIDA-00662_AIC3254 (MISO.1 U1.11), TIDA-00662_MCU (U2.41)
SPI_MOSI: TIDA-00662_AIC3254 (JP62.1), TIDA-00662_MCU (U2.40)
SPI_SCLK: TIDA-00662_AIC3254 (SCLK.1 U1.8), TIDA-00662_MCU (U2.36)
SPI_SS~: TIDA-00662_AIC3254 (JP61.1), TIDA-00662_MCU (U2.39)
USB_Data+: TIDA-00662_MCU (R204.2), TIDA-00662_ExternalInterfaces (D1.2 D1.5 L1.1)
USB_Data-: TIDA-00662_MCU (R206.2), TIDA-00662_ExternalInterfaces (D1.3 L1.4)

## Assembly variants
001: not fitted FID1 FID2 FID3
